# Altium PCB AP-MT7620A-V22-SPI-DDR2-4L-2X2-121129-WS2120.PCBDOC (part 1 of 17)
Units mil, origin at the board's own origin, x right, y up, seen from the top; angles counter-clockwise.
Board outline 7316 x 4279 mil, 4 copper layers (Top, Inner Layer 2, Inner Layer 3, Bottom), stack 35.4 mil thick; 640 components, 473 nets, 2041 pads, 2358 vias.
Unrouted connection lines stored in the file: 11.
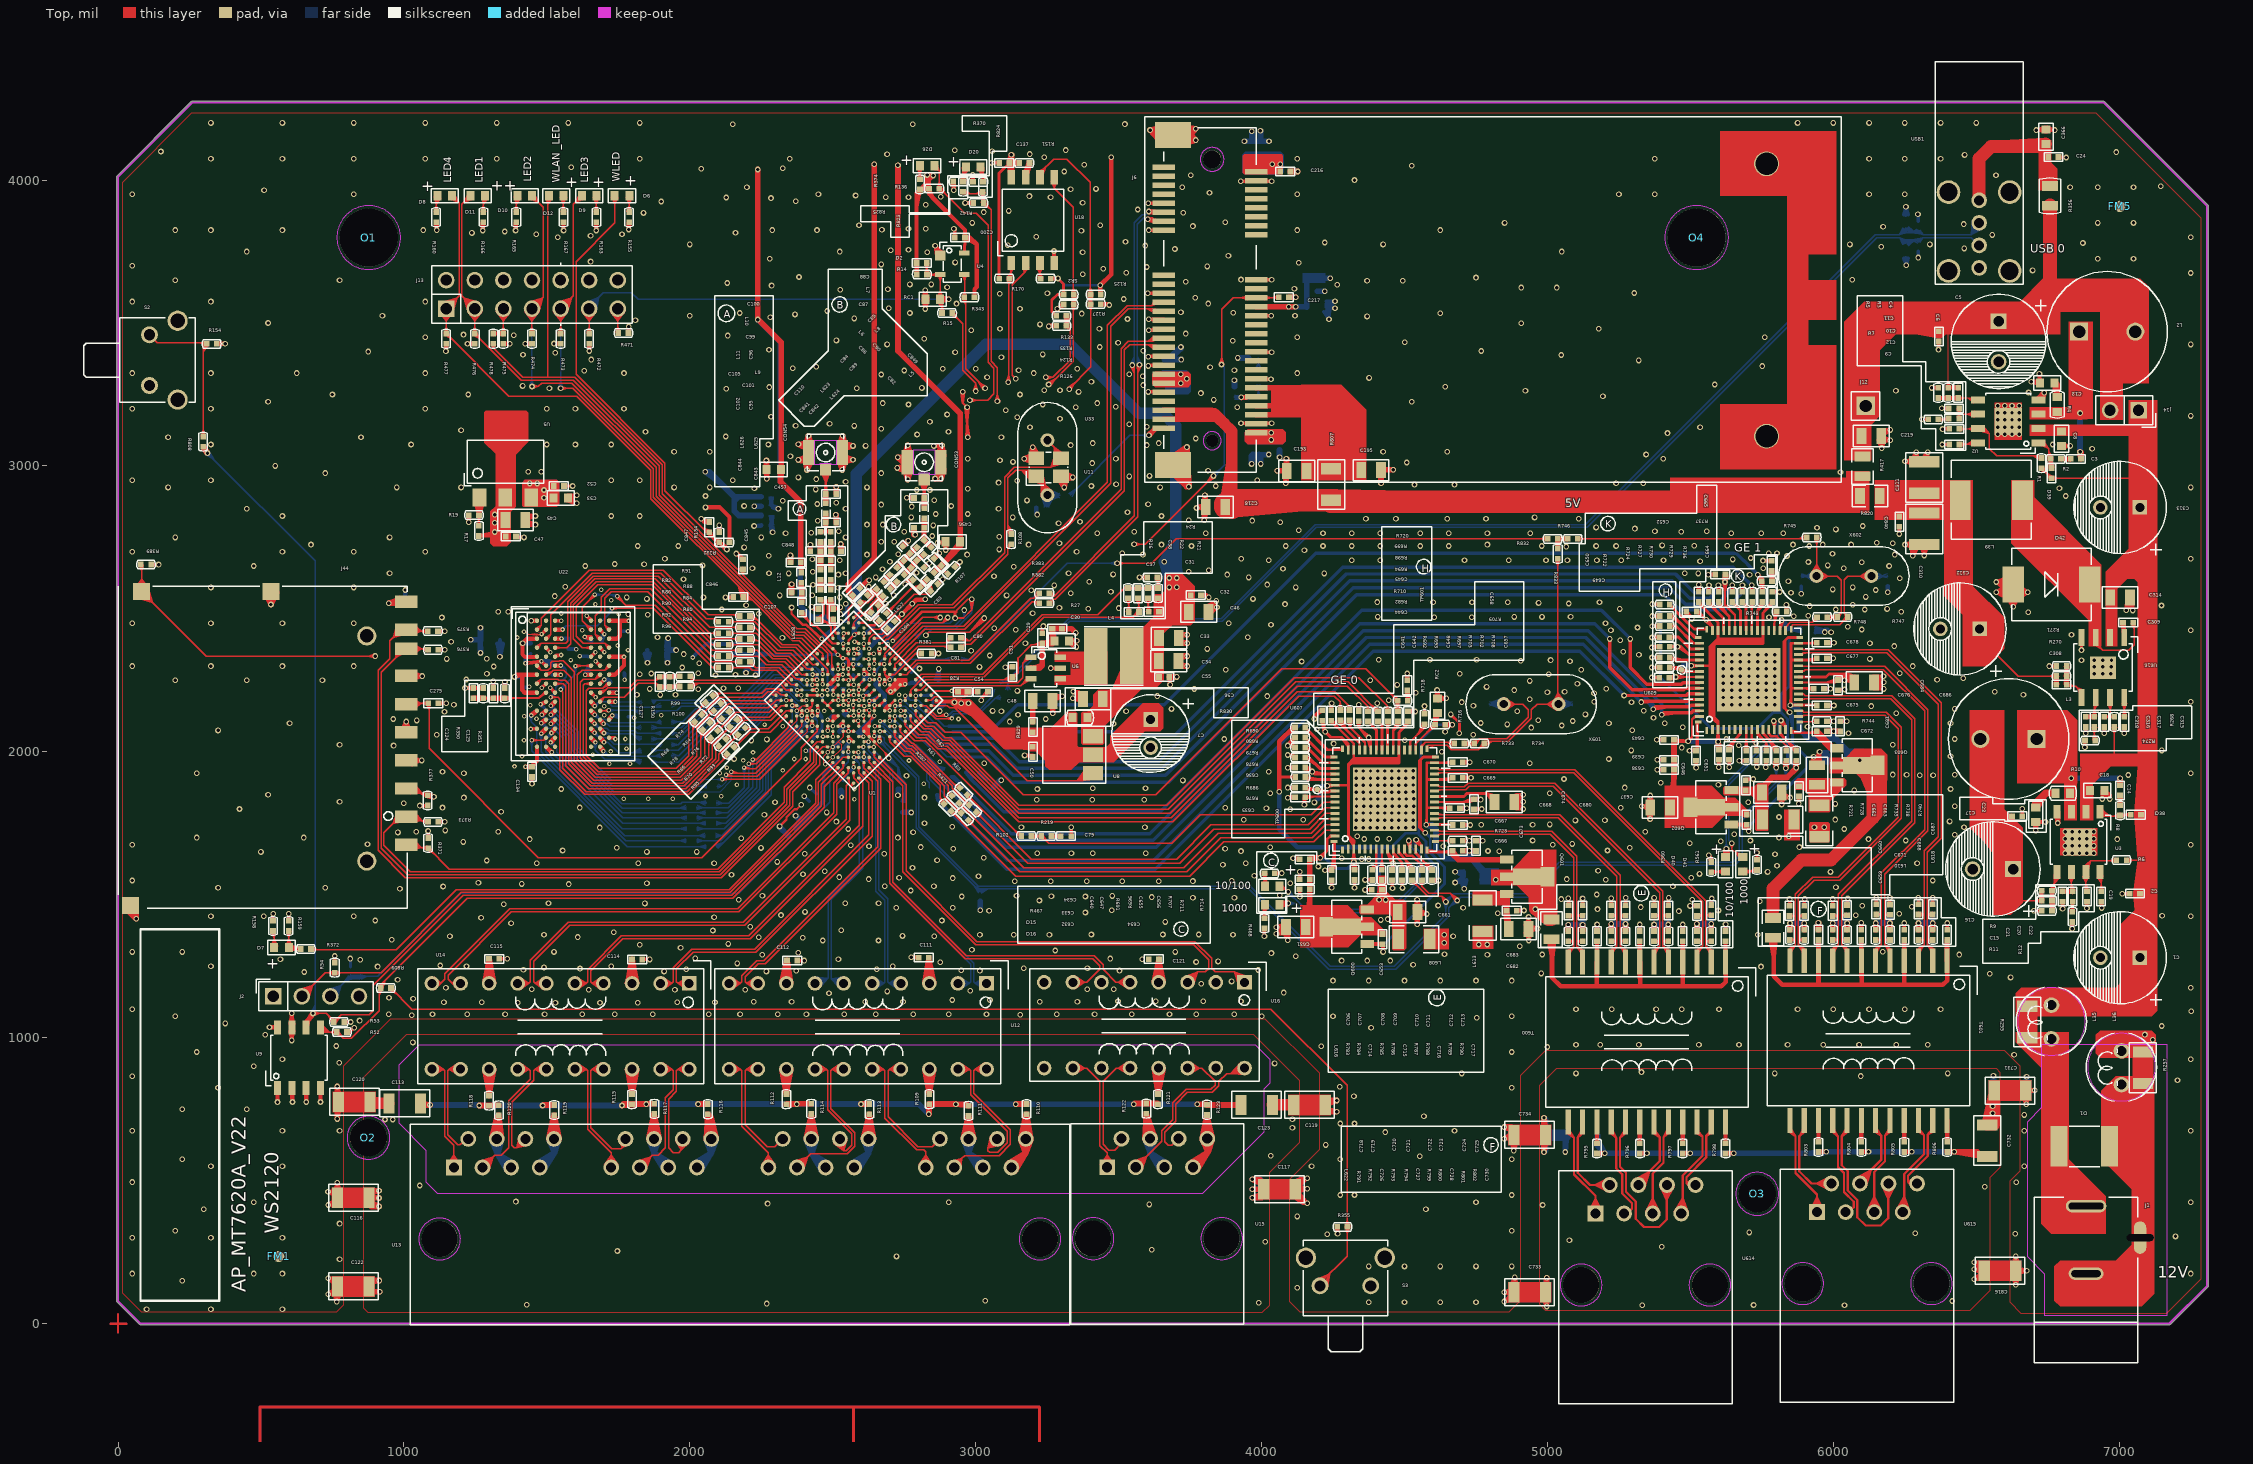
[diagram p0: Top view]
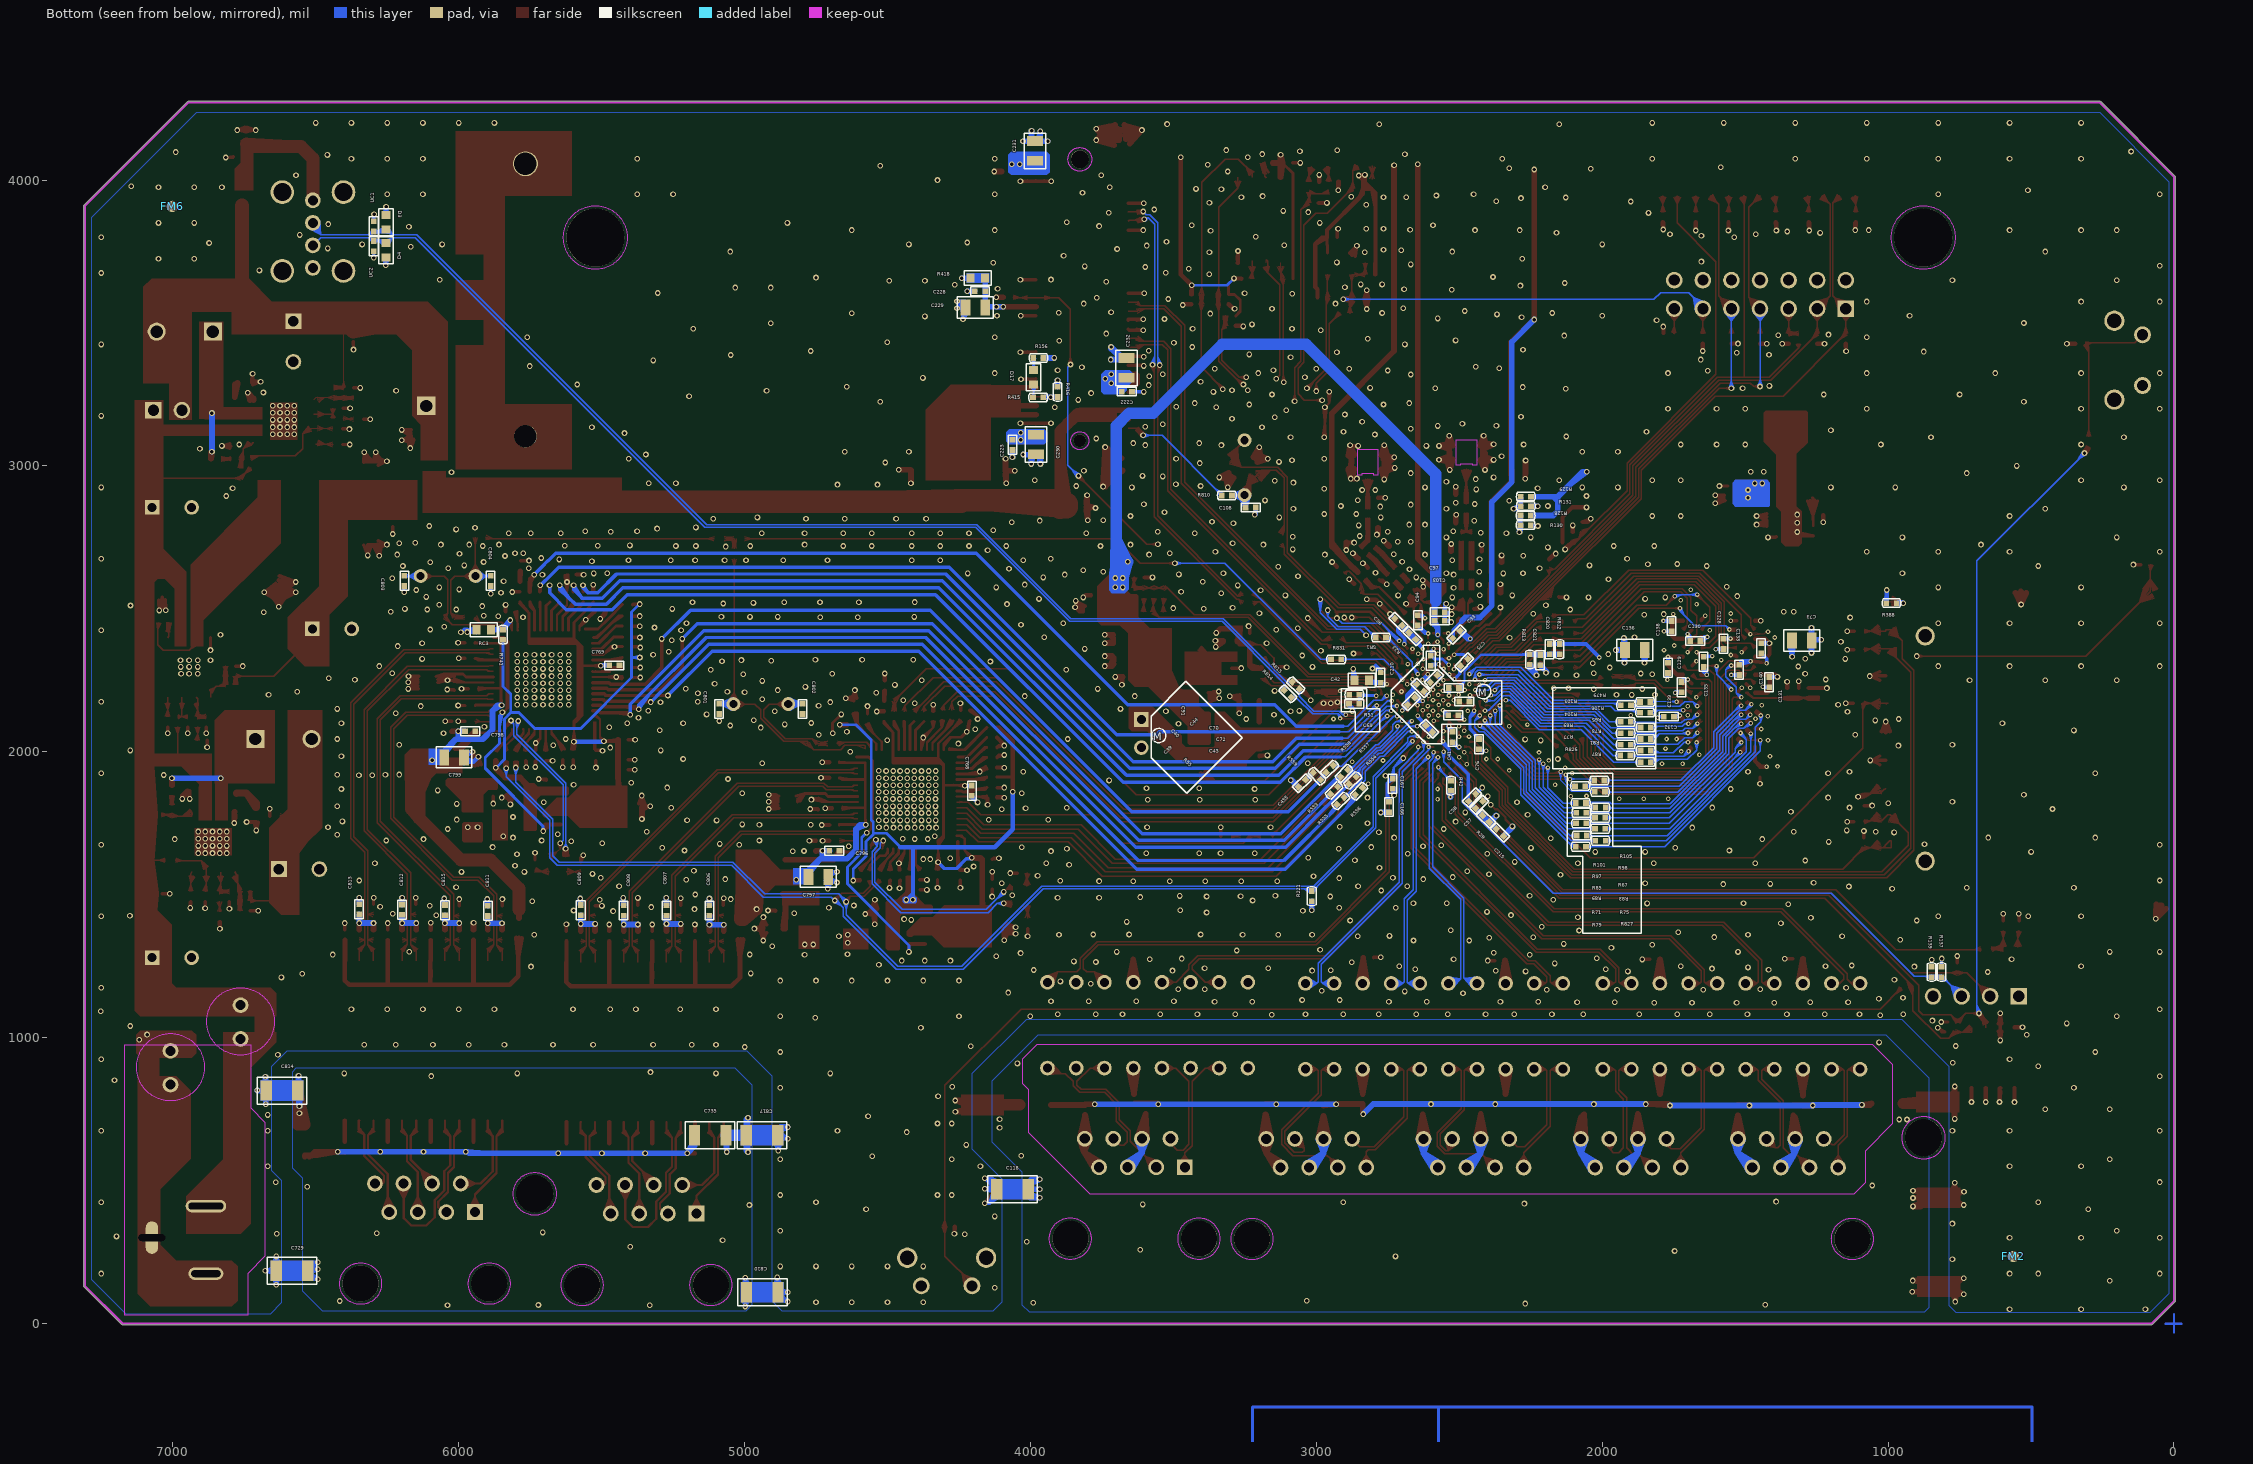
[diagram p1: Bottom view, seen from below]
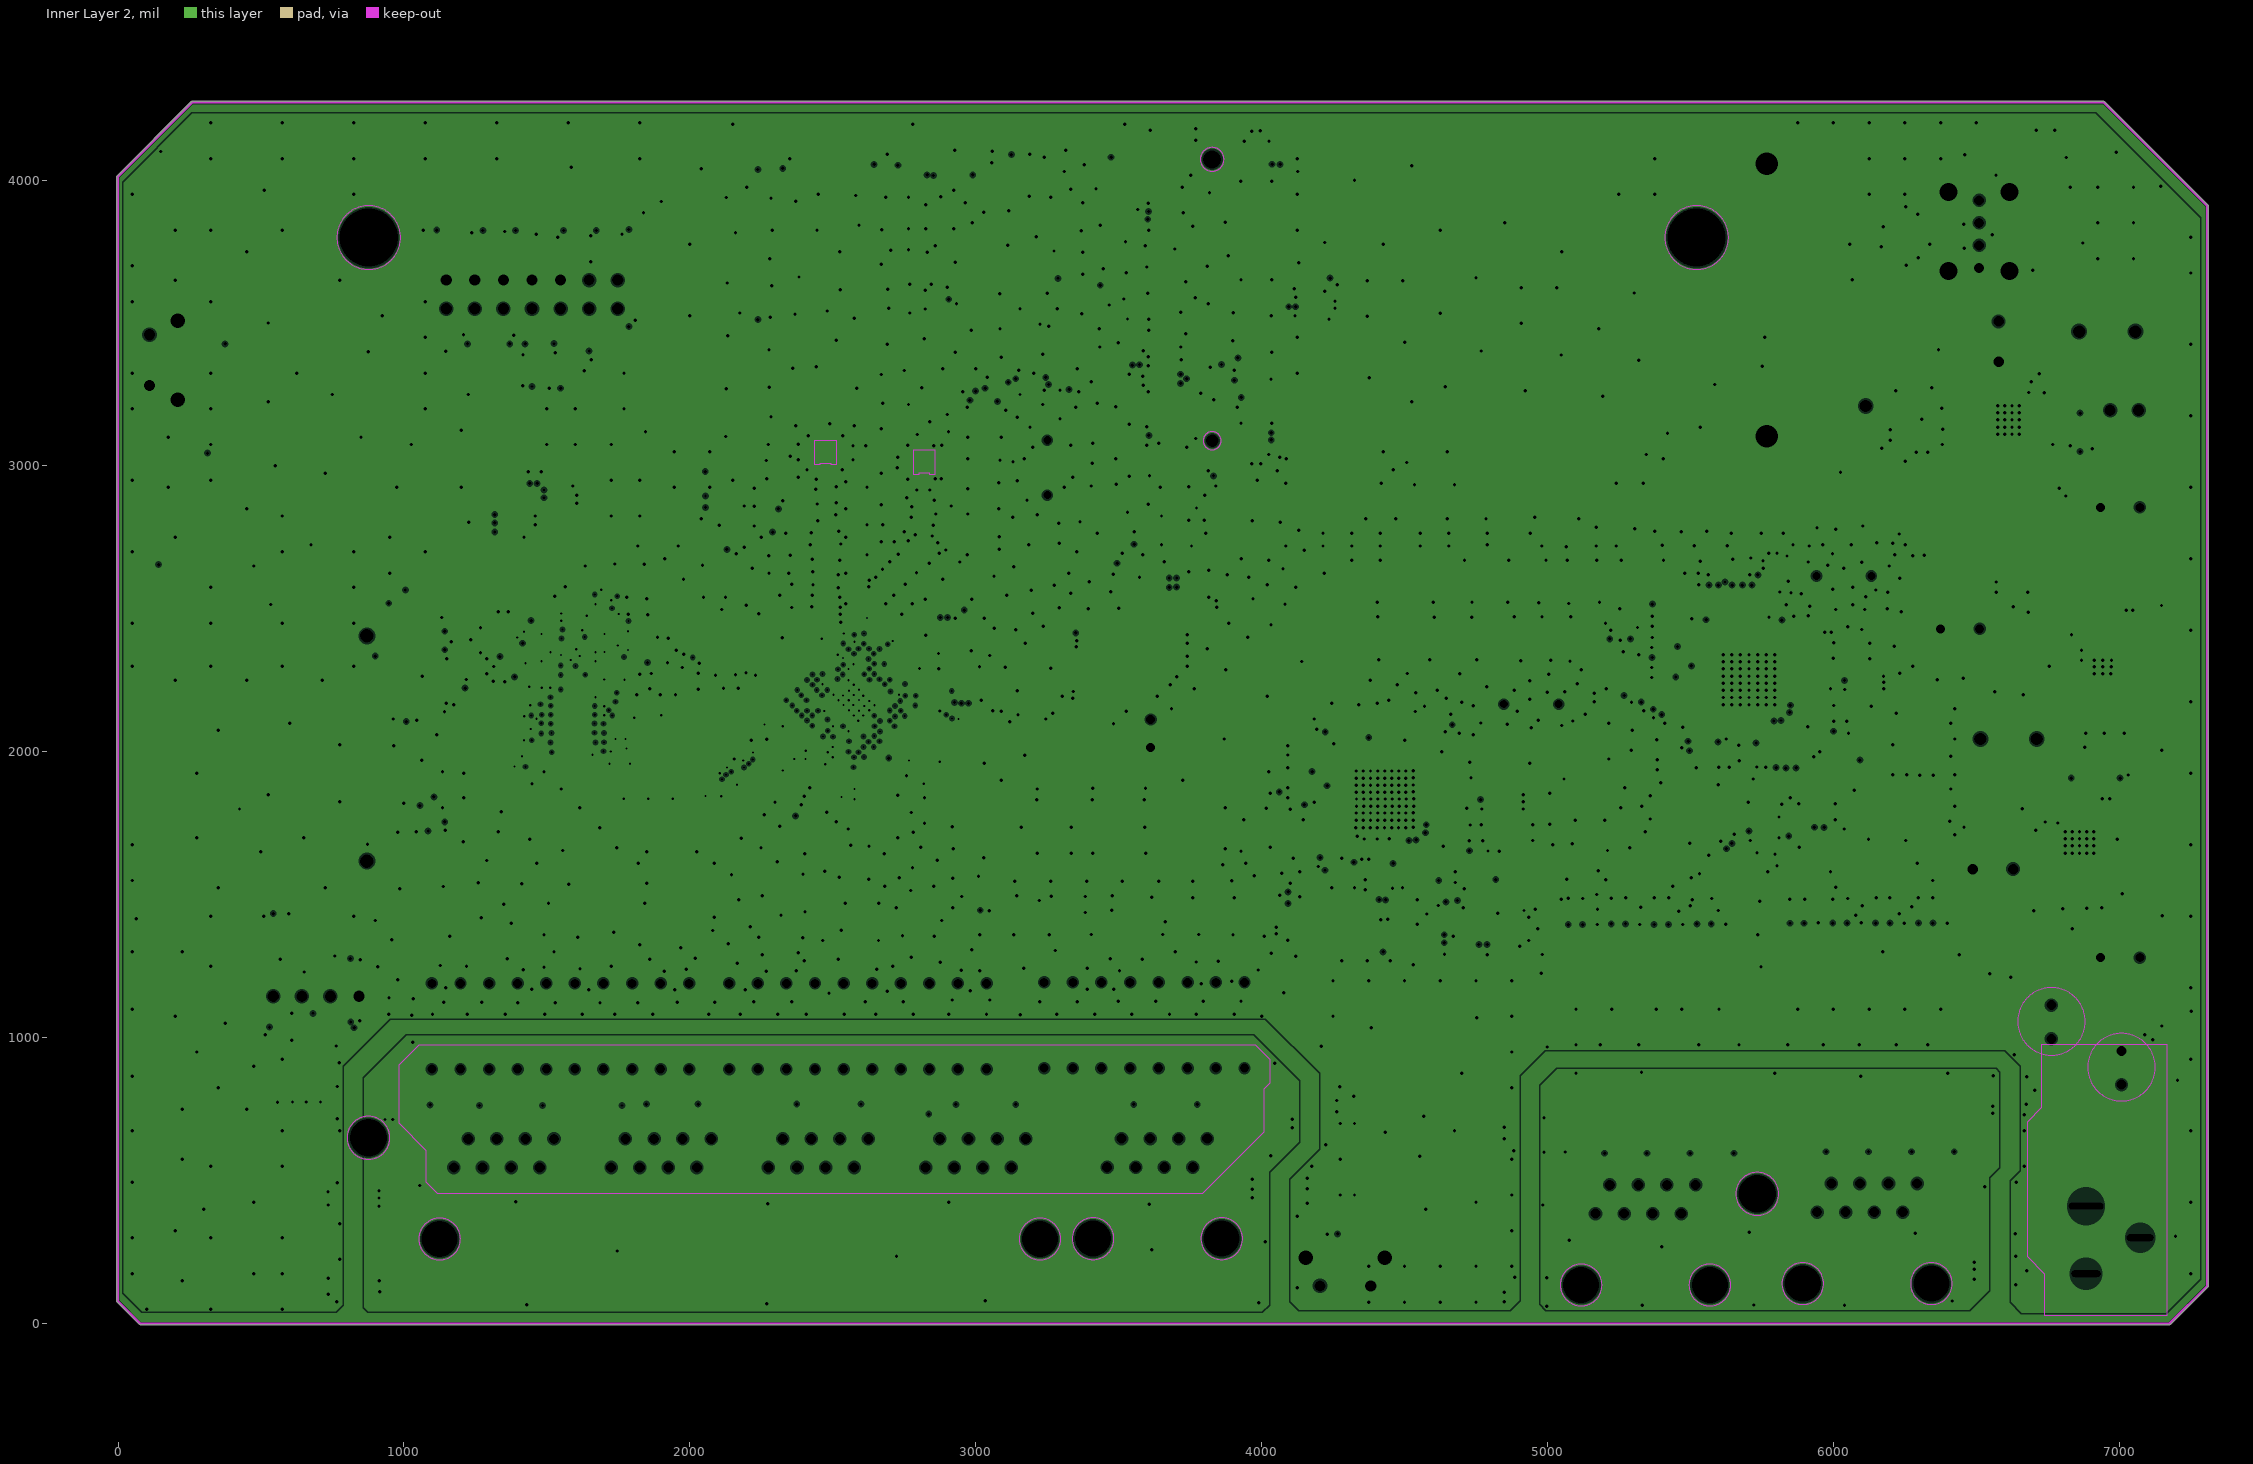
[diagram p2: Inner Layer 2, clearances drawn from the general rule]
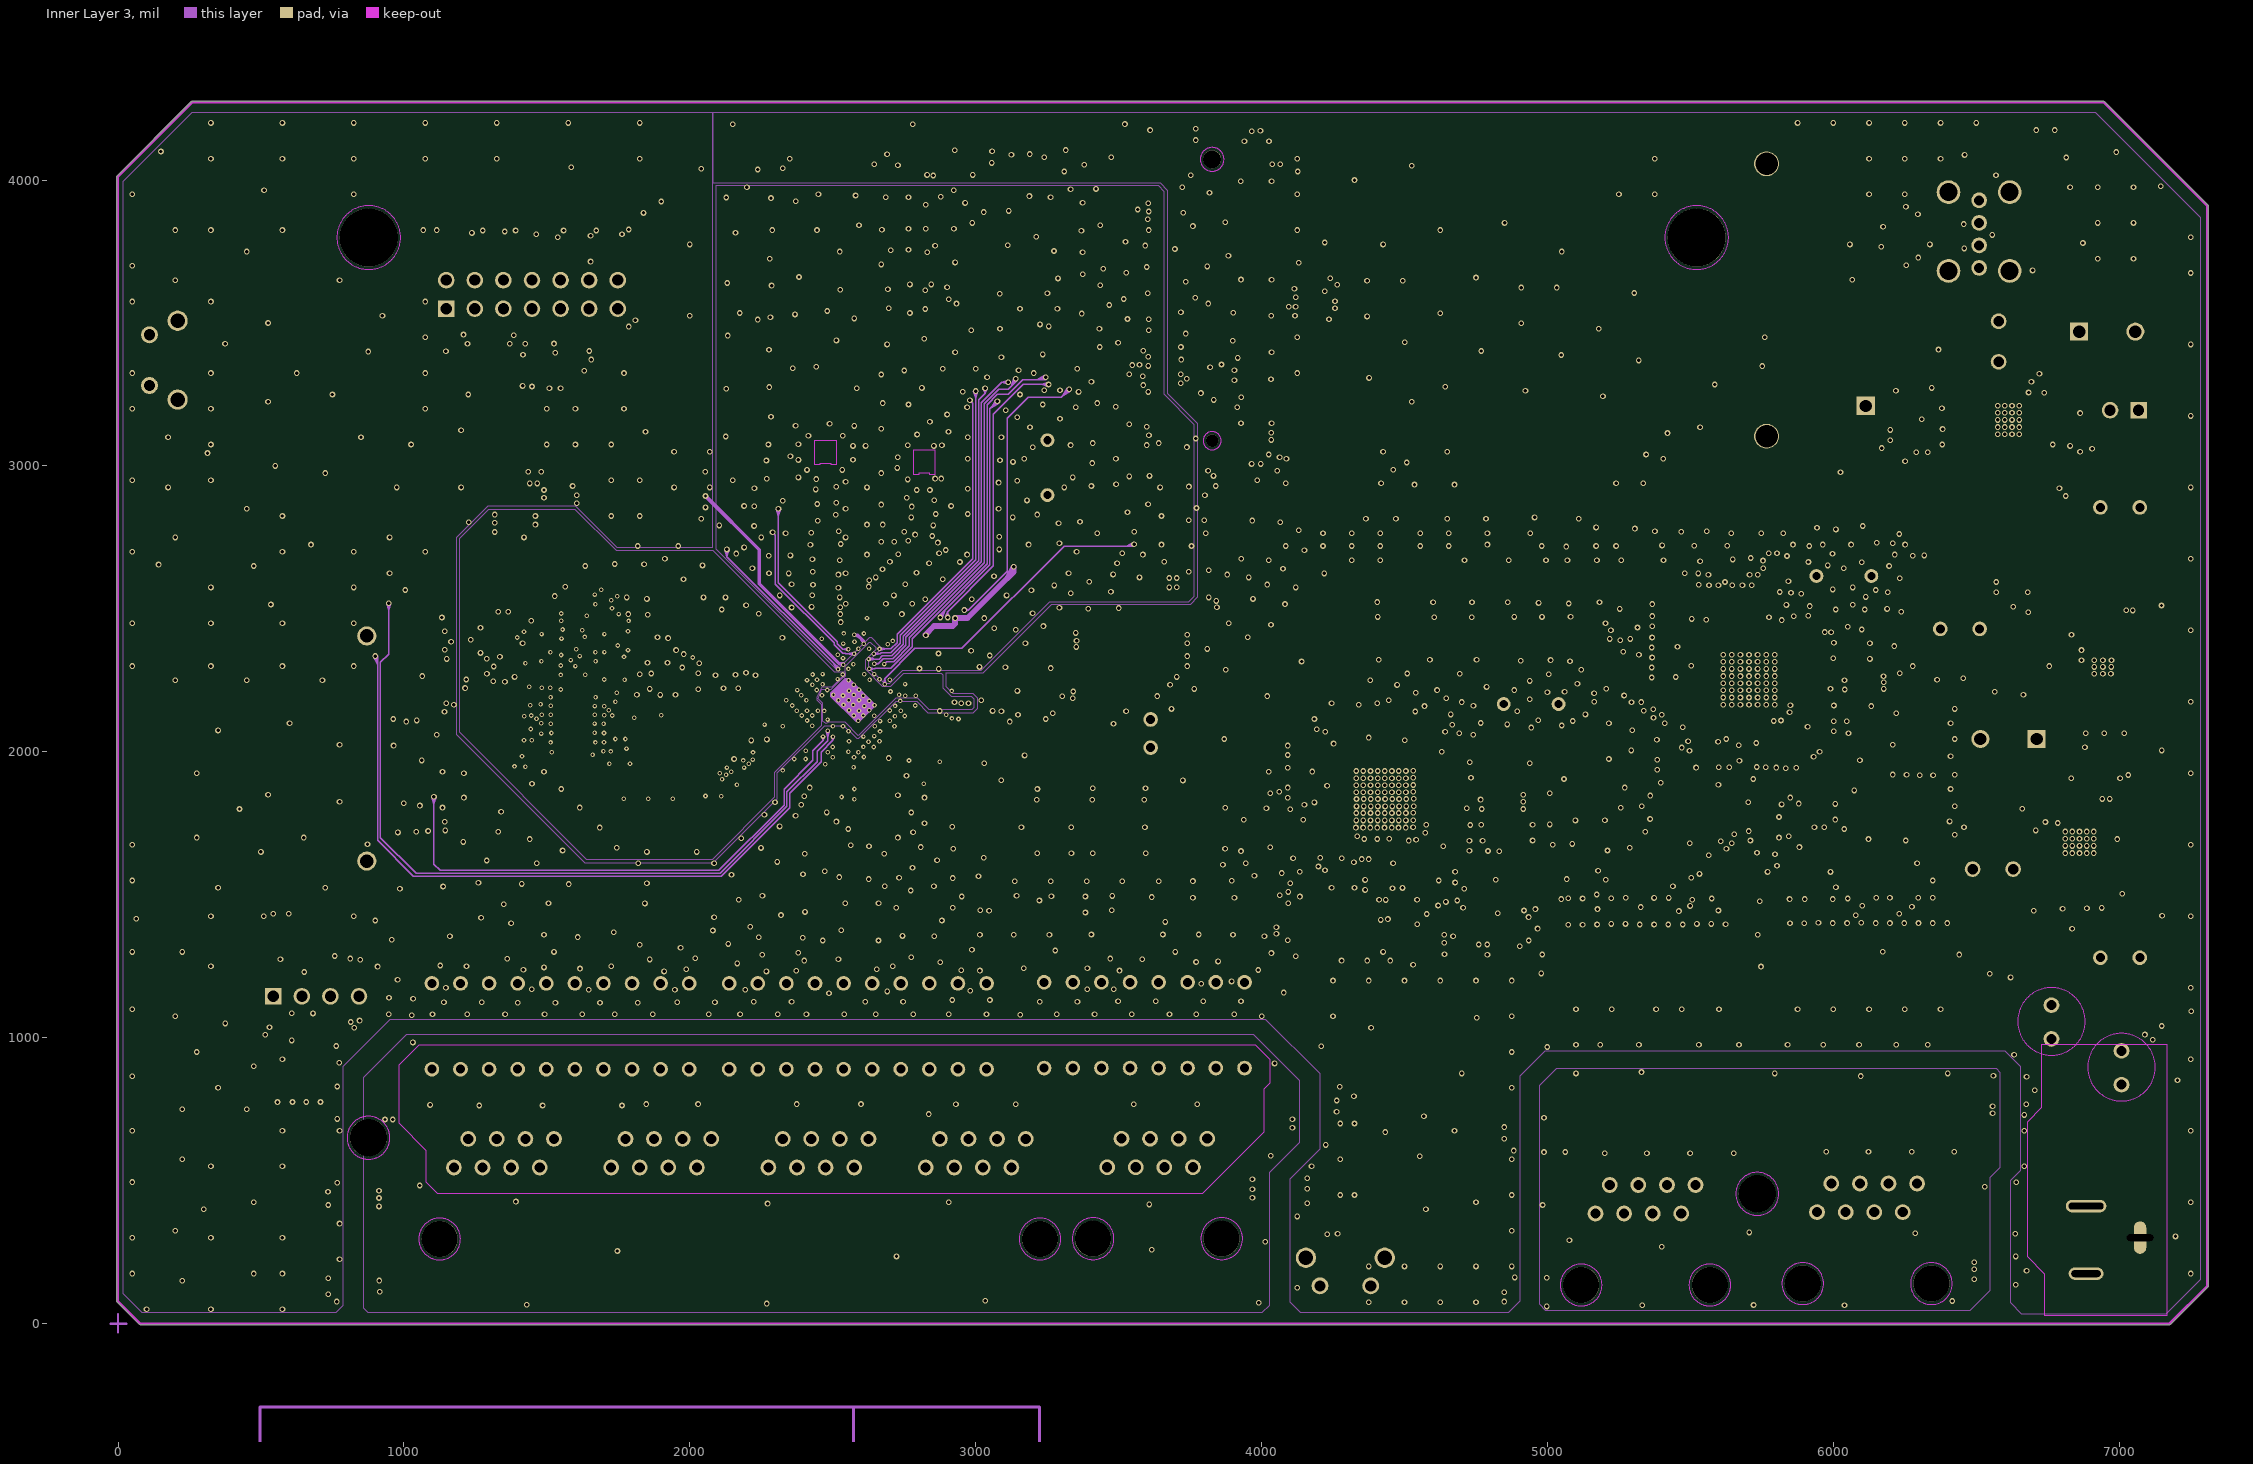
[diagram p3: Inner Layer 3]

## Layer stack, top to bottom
Top: signal copper 1.35
Dielectric: dielectric 10, FR-4, Dk 4.3
Inner Layer 2: plane copper 1.35
Dielectric: dielectric 10, FR-4, Dk 4.3
Inner Layer 3: signal copper 1.35
Dielectric: dielectric 10, FR-4, Dk 4.3
Bottom: signal copper 1.35

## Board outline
-4,78 -2.83,75.17 -2.82,75.16 75.16,-2.82 75.17,-2.83 78,-4 7176,-4 7178.83,-2.83 7178.84,-2.82 7310.82,129.16 7310.83,129.17 7312,132 7312,3909.06 7310.83,3911.89 6948.8,4273.83 6945.97,4275 258.77,4275 255.94,4273.83 -2.83,4014.66 -4,4011.84

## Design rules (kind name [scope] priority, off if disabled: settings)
Clearance "'Classon Layer' PADS rule_125" [InNetClass('DDR') And OnLayer('Top')] p1: gap=7
Clearance "'Classon Layer' PADS rule_124" [InNetClass('DDR') And OnLayer('Top') And IsSMTPin vs IsSMTPin] p2: gap=7
Clearance "'Classon Layer' PADS rule_123" [InNetClass('DDR') And OnLayer('Top')] p3: gap=5
Clearance "'Classon Layer' PADS rule_122" [InNetClass('DDR') And OnLayer('Top') And (IsTrack Or IsArc) vs (IsTrack Or IsArc)] p4: gap=5
Clearance "'Classon Layer' PADS rule_121" [InNetClass('DDR') And OnLayer('Top') vs (IsTrack Or IsArc Or IsThruPin Or IsSMTPin Or IsVia Or IsFill Or InPolygon)] p5: gap=4
Clearance "'Classon Layer' PADS rule_119" [InNetClass('ETH_20') And OnLayer('Bottom')] p6: gap=7
Clearance "'Classon Layer' PADS rule_118" [InNetClass('ETH_20') And OnLayer('Bottom') And IsSMTPin vs IsSMTPin] p7: gap=7
Clearance "'Classon Layer' PADS rule_117" [InNetClass('ETH_20') And OnLayer('Bottom')] p8: gap=5
Clearance "'Classon Layer' PADS rule_116" [InNetClass('ETH_20') And OnLayer('Bottom') And (IsTrack Or IsArc) vs (IsTrack Or IsArc)] p9: gap=5
Clearance "'Classon Layer' PADS rule_115" [InNetClass('ETH_20') And OnLayer('Bottom') vs (IsTrack Or IsArc Or IsThruPin Or IsSMTPin Or IsVia Or IsFill Or InPolygon)] p10: gap=4
Clearance "'Classon Layer' PADS rule_113" [InNetClass('PCIE') And OnLayer('Top')] p11: gap=7
Clearance "'Classon Layer' PADS rule_112" [InNetClass('PCIE') And OnLayer('Top') And IsSMTPin vs IsSMTPin] p12: gap=7
Clearance "'Classon Layer' PADS rule_111" [InNetClass('PCIE') And OnLayer('Top')] p13: gap=6
Clearance "'Classon Layer' PADS rule_110" [InNetClass('PCIE') And OnLayer('Top') And (IsTrack Or IsArc) vs (IsTrack Or IsArc)] p14: gap=6
Clearance "'Classon Layer' PADS rule_109" [InNetClass('PCIE') And OnLayer('Top') vs (IsTrack Or IsArc Or IsThruPin Or IsSMTPin Or IsVia Or IsFill Or InPolygon)] p15: gap=4
Clearance "'Classon Layer' PADS rule_107" [InNetClass('DDR') And OnLayer('Bottom')] p16: gap=7
Clearance "'Classon Layer' PADS rule_106" [InNetClass('DDR') And OnLayer('Bottom') And IsSMTPin vs IsSMTPin] p17: gap=7
Clearance "'Classon Layer' PADS rule_105" [InNetClass('DDR') And OnLayer('Bottom')] p18: gap=5
Clearance "'Classon Layer' PADS rule_104" [InNetClass('DDR') And OnLayer('Bottom') And (IsTrack Or IsArc) vs (IsTrack Or IsArc)] p19: gap=5
Clearance "'Classon Layer' PADS rule_103" [InNetClass('DDR') And OnLayer('Bottom') vs (IsTrack Or IsArc Or IsThruPin Or IsSMTPin Or IsVia Or IsFill Or InPolygon)] p20: gap=4
Clearance "'Classon Layer' PADS rule_101" [InNetClass('ETH_20') And OnLayer('Top')] p21: gap=7
Clearance "'Classon Layer' PADS rule_100" [InNetClass('ETH_20') And OnLayer('Top') And IsSMTPin vs IsSMTPin] p22: gap=7
Clearance "'Classon Layer' PADS rule_99" [InNetClass('ETH_20') And OnLayer('Top')] p23: gap=5
Clearance "'Classon Layer' PADS rule_98" [InNetClass('ETH_20') And OnLayer('Top') And (IsTrack Or IsArc) vs (IsTrack Or IsArc)] p24: gap=5
Clearance "'Classon Layer' PADS rule_97" [InNetClass('ETH_20') And OnLayer('Top') vs (IsTrack Or IsArc Or IsThruPin Or IsSMTPin Or IsVia Or IsFill Or InPolygon)] p25: gap=4
Clearance "'Classon Layer' PADS rule_95" [InNetClass('GE_PHY') And OnLayer('Bottom')] p26: gap=7
Clearance "'Classon Layer' PADS rule_94" [InNetClass('GE_PHY') And OnLayer('Bottom') And IsSMTPin vs IsSMTPin] p27: gap=7
Clearance "'Classon Layer' PADS rule_93" [InNetClass('GE_PHY') And OnLayer('Bottom')] p28: gap=6
Clearance "'Classon Layer' PADS rule_92" [InNetClass('GE_PHY') And OnLayer('Bottom') And (IsTrack Or IsArc) vs (IsTrack Or IsArc)] p29: gap=6
Clearance "'Classon Layer' PADS rule_91" [InNetClass('GE_PHY') And OnLayer('Bottom') vs (IsTrack Or IsArc Or IsThruPin Or IsSMTPin Or IsVia Or IsFill Or InPolygon)] p30: gap=4
Clearance "'Classon Layer' PADS rule_89" [InNetClass('GE_PHY') And OnLayer('Top')] p31: gap=7
Clearance "'Classon Layer' PADS rule_88" [InNetClass('GE_PHY') And OnLayer('Top') And IsSMTPin vs IsSMTPin] p32: gap=7
Clearance "'Classon Layer' PADS rule_87" [InNetClass('GE_PHY') And OnLayer('Top')] p33: gap=6
Clearance "'Classon Layer' PADS rule_86" [InNetClass('GE_PHY') And OnLayer('Top') And (IsTrack Or IsArc) vs (IsTrack Or IsArc)] p34: gap=6
Clearance "'Classon Layer' PADS rule_85" [InNetClass('GE_PHY') And OnLayer('Top') vs (IsTrack Or IsArc Or IsThruPin Or IsSMTPin Or IsVia Or IsFill Or InPolygon)] p35: gap=4
Clearance "'Classon Layer' PADS rule_83" [InNetClass('GE_HP') And OnLayer('Bottom')] p36: gap=7
Clearance "'Classon Layer' PADS rule_82" [InNetClass('GE_HP') And OnLayer('Bottom') And IsSMTPin vs IsSMTPin] p37: gap=7
Clearance "'Classon Layer' PADS rule_81" [InNetClass('GE_HP') And OnLayer('Bottom')] p38: gap=5
Clearance "'Classon Layer' PADS rule_80" [InNetClass('GE_HP') And OnLayer('Bottom') And (IsTrack Or IsArc) vs (IsTrack Or IsArc)] p39: gap=5
Clearance "'Classon Layer' PADS rule_79" [InNetClass('GE_HP') And OnLayer('Bottom') vs (IsTrack Or IsArc Or IsThruPin Or IsSMTPin Or IsVia Or IsFill Or InPolygon)] p40: gap=4
Clearance "'Classon Layer' PADS rule_77" [InNetClass('GE_HP') And OnLayer('Top')] p41: gap=7
Clearance "'Classon Layer' PADS rule_76" [InNetClass('GE_HP') And OnLayer('Top') And IsSMTPin vs IsSMTPin] p42: gap=7
Clearance "'Classon Layer' PADS rule_75" [InNetClass('GE_HP') And OnLayer('Top')] p43: gap=5
Clearance "'Classon Layer' PADS rule_74" [InNetClass('GE_HP') And OnLayer('Top') And (IsTrack Or IsArc) vs (IsTrack Or IsArc)] p44: gap=5
Clearance "'Classon Layer' PADS rule_73" [InNetClass('GE_HP') And OnLayer('Top') vs (IsTrack Or IsArc Or IsThruPin Or IsSMTPin Or IsVia Or IsFill Or InPolygon)] p45: gap=4
Clearance "'Classon Layer' PADS rule_71" [InNetClass('RF') And OnLayer('Bottom')] p46: gap=7
Clearance "'Classon Layer' PADS rule_70" [InNetClass('RF') And OnLayer('Bottom') And IsSMTPin vs IsSMTPin] p47: gap=7
Clearance "'Classon Layer' PADS rule_69" [InNetClass('RF') And OnLayer('Bottom')] p48: gap=5
Clearance "'Classon Layer' PADS rule_68" [InNetClass('RF') And OnLayer('Bottom') And (IsTrack Or IsArc) vs (IsTrack Or IsArc)] p49: gap=5
Clearance "'Classon Layer' PADS rule_67" [InNetClass('RF') And OnLayer('Bottom') vs (IsTrack Or IsArc Or IsThruPin Or IsSMTPin Or IsVia Or IsFill Or InPolygon)] p50: gap=4
Clearance "'Classon Layer' PADS rule_65" [InNetClass('RF') And OnLayer('Top')] p51: gap=7
Clearance "'Classon Layer' PADS rule_64" [InNetClass('RF') And OnLayer('Top') And IsSMTPin vs IsSMTPin] p52: gap=7
Clearance "'Classon Layer' PADS rule_63" [InNetClass('RF') And OnLayer('Top')] p53: gap=5
Clearance "'Classon Layer' PADS rule_62" [InNetClass('RF') And OnLayer('Top') And (IsTrack Or IsArc) vs (IsTrack Or IsArc)] p54: gap=5
Clearance "'Classon Layer' PADS rule_61" [InNetClass('RF') And OnLayer('Top') vs (IsTrack Or IsArc Or IsThruPin Or IsSMTPin Or IsVia Or IsFill Or InPolygon)] p55: gap=4
Clearance "'Classon Layer' PADS rule_59" [InNetClass('PHY_IC') And OnLayer('Bottom')] p56: gap=7
Clearance "'Classon Layer' PADS rule_58" [InNetClass('PHY_IC') And OnLayer('Bottom') And IsSMTPin vs IsSMTPin] p57: gap=7
Clearance "'Classon Layer' PADS rule_57" [InNetClass('PHY_IC') And OnLayer('Bottom')] p58: gap=6
Clearance "'Classon Layer' PADS rule_56" [InNetClass('PHY_IC') And OnLayer('Bottom') And (IsTrack Or IsArc) vs (IsTrack Or IsArc)] p59: gap=6
Clearance "'Classon Layer' PADS rule_55" [InNetClass('PHY_IC') And OnLayer('Bottom') vs (IsTrack Or IsArc Or IsThruPin Or IsSMTPin Or IsVia Or IsFill Or InPolygon)] p60: gap=4
Clearance "'Classon Layer' PADS rule_53" [InNetClass('PHY_IC') And OnLayer('Top')] p61: gap=7
Clearance "'Classon Layer' PADS rule_52" [InNetClass('PHY_IC') And OnLayer('Top') And IsSMTPin vs IsSMTPin] p62: gap=7
Clearance "'Classon Layer' PADS rule_51" [InNetClass('PHY_IC') And OnLayer('Top')] p63: gap=6
Clearance "'Classon Layer' PADS rule_50" [InNetClass('PHY_IC') And OnLayer('Top') And (IsTrack Or IsArc) vs (IsTrack Or IsArc)] p64: gap=6
Clearance "'Classon Layer' PADS rule_49" [InNetClass('PHY_IC') And OnLayer('Top') vs (IsTrack Or IsArc Or IsThruPin Or IsSMTPin Or IsVia Or IsFill Or InPolygon)] p65: gap=4
Clearance "'Classon Layer' PADS rule_47" [InNetClass('USB') And OnLayer('Bottom')] p66: gap=7
Clearance "'Classon Layer' PADS rule_46" [InNetClass('USB') And OnLayer('Bottom') And IsSMTPin vs IsSMTPin] p67: gap=7
Clearance "'Classon Layer' PADS rule_45" [InNetClass('USB') And OnLayer('Bottom')] p68: gap=4.5
Clearance "'Classon Layer' PADS rule_44" [InNetClass('USB') And OnLayer('Bottom') And (IsTrack Or IsArc) vs (IsTrack Or IsArc)] p69: gap=4.5
Clearance "'Classon Layer' PADS rule_43" [InNetClass('USB') And OnLayer('Bottom') vs (IsTrack Or IsArc Or IsThruPin Or IsSMTPin Or IsVia Or IsFill Or InPolygon)] p70: gap=4
Clearance "'Classon Layer' PADS rule_41" [InNetClass('PHY_ETH') And OnLayer('Top')] p71: gap=7
Clearance "'Classon Layer' PADS rule_40" [InNetClass('PHY_ETH') And OnLayer('Top') And IsSMTPin vs IsSMTPin] p72: gap=7
Clearance "'Classon Layer' PADS rule_39" [InNetClass('PHY_ETH') And OnLayer('Top')] p73: gap=6
Clearance "'Classon Layer' PADS rule_38" [InNetClass('PHY_ETH') And OnLayer('Top') And (IsTrack Or IsArc) vs (IsTrack Or IsArc)] p74: gap=6
Clearance "'Classon Layer' PADS rule_37" [InNetClass('PHY_ETH') And OnLayer('Top') vs (IsTrack Or IsArc Or IsThruPin Or IsSMTPin Or IsVia Or IsFill Or InPolygon)] p75: gap=4
Clearance "'Classon Layer' PADS rule_35" [InNetClass('PCIE') And OnLayer('Bottom')] p76: gap=7
Clearance "'Classon Layer' PADS rule_34" [InNetClass('PCIE') And OnLayer('Bottom') And IsSMTPin vs IsSMTPin] p77: gap=7
Clearance "'Classon Layer' PADS rule_33" [InNetClass('PCIE') And OnLayer('Bottom')] p78: gap=5
Clearance "'Classon Layer' PADS rule_32" [InNetClass('PCIE') And OnLayer('Bottom') And (IsTrack Or IsArc) vs (IsTrack Or IsArc)] p79: gap=5
Clearance "'Classon Layer' PADS rule_31" [InNetClass('PCIE') And OnLayer('Bottom') vs (IsTrack Or IsArc Or IsThruPin Or IsSMTPin Or IsVia Or IsFill Or InPolygon)] p80: gap=4
Clearance "'Classon Layer' PADS rule_29" [InNetClass('USB') And OnLayer('Top')] p81: gap=7
Clearance "'Classon Layer' PADS rule_28" [InNetClass('USB') And OnLayer('Top') And IsSMTPin vs IsSMTPin] p82: gap=7
Clearance "'Classon Layer' PADS rule_27" [InNetClass('USB') And OnLayer('Top')] p83: gap=4.5
Clearance "'Classon Layer' PADS rule_26" [InNetClass('USB') And OnLayer('Top') And (IsTrack Or IsArc) vs (IsTrack Or IsArc)] p84: gap=4.5
Clearance "'Classon Layer' PADS rule_25" [InNetClass('USB') And OnLayer('Top') vs (IsTrack Or IsArc Or IsThruPin Or IsSMTPin Or IsVia Or IsFill Or InPolygon)] p85: gap=4
Clearance "'Classon Layer' PADS rule_23" [InNetClass('PHY_ETH') And OnLayer('Bottom')] p86: gap=7
Clearance "'Classon Layer' PADS rule_22" [InNetClass('PHY_ETH') And OnLayer('Bottom') And IsSMTPin vs IsSMTPin] p87: gap=7
Clearance "'Classon Layer' PADS rule_21" [InNetClass('PHY_ETH') And OnLayer('Bottom')] p88: gap=6
Clearance "'Classon Layer' PADS rule_20" [InNetClass('PHY_ETH') And OnLayer('Bottom') And (IsTrack Or IsArc) vs (IsTrack Or IsArc)] p89: gap=6
Clearance "'Classon Layer' PADS rule_19" [InNetClass('PHY_ETH') And OnLayer('Bottom') vs (IsTrack Or IsArc Or IsThruPin Or IsSMTPin Or IsVia Or IsFill Or InPolygon)] p90: gap=4
Clearance "'Default' PADS rule_18" [All] p91: gap=7
Clearance "'Default' PADS rule_17" [IsSMTPin vs IsSMTPin] p92: gap=7
Clearance "'Default' PADS rule_16" [All] p93: gap=4
ComponentClearance "'Default' PADS rule_12" [All] p1: gap=0 collisioncheckmode=3 verticalgap=10 showdistances=FALSE
FlightTimeFalling "'Default' PADS rule_10" [All] p1: maximum=10.00
FlightTimeRising "'Default' PADS rule_9" [All] p1: maximum=10.00
Length "'Default' PADS rule_5" [All] p1: maxlimit=50000 minlimit=0
MatchedLengths "'Default' PADS rule_11" [InNetClass('All Nets')] p1: tolerance=200 checknetsindiffpair=TRUE checkdiffpairvsdiffpair=TRUE checkothers=TRUE
MaxMinImpedance "'Default' PADS rule_8" [All] p1: minimum=50.00 maximum=150.0
ParallelSegment "'Default' PADS rule_7" [All] p1: limit=1000 gap=200
ParallelSegment "'Default' PADS rule_6" [All] p2: limit=1000 gap=200
PlaneClearance "Power Plane Clearance for L35-1" [(Name='L35-1') Or (Name='L35-2') Or (Name='L36-1') Or (Name='L36-2')] p1: clearance=15 // PAD - Power Plane Clearance
PlaneClearance "'Default' PADS rule_14" [All] p2: clearance=6
PlaneConnect "Power Plane Connect Style for L35-1" [(Name='L35-1')] p1: planeconnectstyle=Relief reliefexpansion=10 reliefentries=4 reliefconductorwidth=25 reliefairgap=10
PlaneConnect "Power Plane Connect Style for J6-57" [(Name='J6-57')] p2: planeconnectstyle=Relief reliefexpansion=3.94 reliefentries=4 reliefconductorwidth=15 reliefairgap=0
PlaneConnect "Power Plane Connect Style - pads with no thermal" [(Name='J13-12') Or (Name='J44-H2') Or (Name='J44-H1') Or (Name='J6-55') Or (Name='J6-56') Or (Name='O1-1') Or (Name='O2-1') Or (Name='O3-1') Or (Name='O4-1') Or (Name='U13-33') Or (Name='U13-34') Or (Name='U15-9') Or (Name='U15-10') Or (Name='U16-2') Or (Name='U16-6') Or (Name='U16-8') Or (Name='U16-9') Or (Name='U16-11') Or (Name='U16-15') Or (Name='U614-9') Or (Name='U614-10') Or (Name='U615-9') Or (Name='U615-10')] p3: planeconnectstyle=NoConnect reliefexpansion=20 reliefentries=4 reliefconductorwidth=10 reliefairgap=10 // PAD - No Thermal Connect Rule
PlaneConnect "Power Plane Connect Style - from global settings" [All] p4: planeconnectstyle=Relief reliefexpansion=20 reliefentries=2 reliefconductorwidth=15 reliefairgap=10
PolygonConnect [All] p1: connectstyle=Relief reliefconductorwidth=10 reliefentries=4 polygonreliefangle="90 Angle"
RoutingLayers "'Default' PADS rule_3" [All] p1: top layer_v5=TRUE mid layer 1_v5=TRUE bottom layer_v5=TRUE
RoutingPriority "'Default' PADS rule_2" [All] p1: routingpriority=3
RoutingTopology "'Default' PADS rule" [All] p1: topology=Shortest
RoutingVias "'Default' PADS rule_4" [All] p1: holewidth=12 width=20 viastyle="Through Hole" minholewidth=12 minwidth=20 maxholewidth=12 maxwidth=20
SMDToPlane "'Default' PADS rule_15" [All] p1: distance=20000
SilkscreenOverComponentPads [All] p1: minsilkscreentomaskgap=10
SolderMaskExpansion "Solder Mask Expansion from CAM settings" [All] p1: expansion=2
TestPointUsage [All] p1: valid=0 allowmultiple=FALSE
Testpoint [All] p1: side=15 testpointundercomponent=TRUE minsize=40 maxsize=100 preferedsize=60 minholesize=0 maxholesize=40 preferedholesize=32 testpointgrid=1 style=1023 order=0-112345678
Width "'Classon Layer' PADS rule_120" [InNetClass('DDR') And OnLayer('Top')] p1: maxlimit=200 minlimit=3 preferedwidth=4.5
Width "'Classon Layer' PADS rule_114" [InNetClass('ETH_20') And OnLayer('Bottom')] p2: maxlimit=200 minlimit=3 preferedwidth=20
Width "'Classon Layer' PADS rule_108" [InNetClass('PCIE') And OnLayer('Top')] p3: maxlimit=150 minlimit=3 preferedwidth=5
Width "'Classon Layer' PADS rule_102" [InNetClass('DDR') And OnLayer('Bottom')] p4: maxlimit=200 minlimit=3 preferedwidth=4.5
Width "'Classon Layer' PADS rule_96" [InNetClass('ETH_20') And OnLayer('Top')] p5: maxlimit=200 minlimit=3 preferedwidth=20
Width "'Classon Layer' PADS rule_90" [InNetClass('GE_PHY') And OnLayer('Bottom')] p6: maxlimit=200 minlimit=3 preferedwidth=5
Width "'Classon Layer' PADS rule_84" [InNetClass('GE_PHY') And OnLayer('Top')] p7: maxlimit=200 minlimit=3 preferedwidth=5
Width "'Classon Layer' PADS rule_78" [InNetClass('GE_HP') And OnLayer('Bottom')] p8: maxlimit=200 minlimit=3 preferedwidth=8
Width "'Classon Layer' PADS rule_72" [InNetClass('GE_HP') And OnLayer('Top')] p9: maxlimit=200 minlimit=3 preferedwidth=8
Width "'Classon Layer' PADS rule_66" [InNetClass('RF') And OnLayer('Bottom')] p10: maxlimit=200 minlimit=3 preferedwidth=8
Width "'Classon Layer' PADS rule_60" [InNetClass('RF') And OnLayer('Top')] p11: maxlimit=200 minlimit=3 preferedwidth=8
Width "'Classon Layer' PADS rule_54" [InNetClass('PHY_IC') And OnLayer('Bottom')] p12: maxlimit=200 minlimit=3 preferedwidth=5
Width "'Classon Layer' PADS rule_48" [InNetClass('PHY_IC') And OnLayer('Top')] p13: maxlimit=200 minlimit=3 preferedwidth=5
Width "'Classon Layer' PADS rule_42" [InNetClass('USB') And OnLayer('Bottom')] p14: maxlimit=200 minlimit=3 preferedwidth=5
Width "'Classon Layer' PADS rule_36" [InNetClass('PHY_ETH') And OnLayer('Top')] p15: maxlimit=200 minlimit=3 preferedwidth=5
Width "'Classon Layer' PADS rule_30" [InNetClass('PCIE') And OnLayer('Bottom')] p16: maxlimit=200 minlimit=3 preferedwidth=5
Width "'Classon Layer' PADS rule_24" [InNetClass('USB') And OnLayer('Top')] p17: maxlimit=200 minlimit=3 preferedwidth=5
Width "'Classon Layer' PADS rule" [InNetClass('PHY_ETH') And OnLayer('Bottom')] p18: maxlimit=200 minlimit=3 preferedwidth=5
Width "'Default' PADS rule_13" [All] p19: maxlimit=200 minlimit=3 preferedwidth=4
17 further rules are at their usual default settings.

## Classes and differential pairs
net class DDR: CLK_N CLK_P DDR_BA0 DDR_BA1 DDR_BA2 DDR_CLK_N_1-CPU-RT0 DDR_CLK_P_1-CPU-RT0 DDR_MCKE DDR_MDQM0 DDR_MDQM1 DDR_MDQS0 DDR_MDQS1 DDR_WEN MA1_1-CPU-RT0 MA3_1-CPU-RT0 MA5_1-CPU-RT0 MA7_1-CPU-RT0 MA9_1-CPU-RT0 MA10_1-CPU-RT0 MA12_1-CPU-RT0 MADDR1 MADDR3 MADDR5 MADDR7 MADDR9 MADDR10 MADDR12 MBA0_1-CPU-RT0 MBA1_1-CPU-RT0 MBA2_1-CPU-RT0 MCKE_1-CPU-RT0 MD0_1-CPU-RT0 MD1_1-CPU-RT0 MD2_1-CPU-RT0 MD3_1-CPU-RT0 MD4_1-CPU-RT0 MD5_1-CPU-RT0 MD6_1-CPU-RT0 MD7_1-CPU-RT0 MD8_1-CPU-RT0 MD9_1-CPU-RT0 MD10_1-CPU-RT0 MD11_1-CPU-RT0 MD12_1-CPU-RT0 MD13_1-CPU-RT0 MD14_1-CPU-RT0 MD15_1-CPU-RT0 MDATA0 MDATA1 MDATA2 MDATA3 MDATA4 MDATA5 MDATA6 MDATA7 MDATA8 MDATA9 MDATA10 MDATA11 MDATA12 MDATA13 MDATA14 MDATA15 MDQM0_1-CPU-RT0 MDQM1_1-CPU-RT0 MDQS0_1-CPU-RT0 MDQS1_1-CPU-RT0 MWE_N_1-CPU-RT0
net class ETH_20: CHGND CMT0_4-ETHERNET CMT1_4-ETHERNET CMT2_4-ETHERNET CMT3_4-ETHERNET CMT4_4-ETHERNET LANP0_C1_4-ETHERNET LANP0_C2_4-ETHERNET LANP1_C1_4-ETHERNET LANP1_C2_4-ETHERNET LANP2_C1_4-ETHERNET LANP2_C2_4-ETHERNET LANP3_C1_4-ETHERNET LANP3_C2_4-ETHERNET P1_4-ETHERNET WAN_C1_4-ETHERNET WAN_C2_4-ETHERNET
net class GE_HP: GP1_GE_2_4-ETHERNET GP1_GE_4-ETHERNET GP2_GE_2_4-ETHERNET GP2_GE_4-ETHERNET GP3_GE_2_4-ETHERNET GP3_GE_4-ETHERNET GP4_GE_2_4-ETHERNET GP4_GE_4-ETHERNET GP5_GE_2_4-ETHERNET GP5_GE_4-ETHERNET GP6_GE_2_4-ETHERNET GP6_GE_4-ETHERNET GP7_GE_2_4-ETHERNET GP7_GE_4-ETHERNET GP8_GE_2_4-ETHERNET GP8_GE_4-ETHERNET PMCT1_GE_2_4-ETHERNET PMCT1_GE_4-ETHERNET PMCT2_GE_2_4-ETHERNET PMCT2_GE_4-ETHERNET PMCT3_GE_2_4-ETHERNET PMCT3_GE_4-ETHERNET PMCT4_GE_2_4-ETHERNET PMCT4_GE_4-ETHERNET PMCT_HV_GE_4-ETHERNET
net class GE_PHY: CHANNEL_A+ CHANNEL_A+_2 CHANNEL_A- CHANNEL_A-_2 CHANNEL_B+ CHANNEL_B+_2 CHANNEL_B- CHANNEL_B-_2 CHANNEL_C+ CHANNEL_C+_2 CHANNEL_C- CHANNEL_C-_2 CHANNEL_D+ CHANNEL_D+_2 CHANNEL_D- CHANNEL_D-_2
net class PCIE: APCK_RFCKO_N APCK_RFCKO_P APCK_RFCKON_1-CPU-RT0 APCK_RFCKOP_1-CPU-RT0 PCIE_RXN PCIE_RXP PCIE_TX_N PCIE_TX_P PCIE_TXN_1-CPU-RT0 PCIE_TXP_1-CPU-RT0
net class PHY_ETH: MA0+_4-ETHERNET MA0-_4-ETHERNET MA1+_4-ETHERNET MA1-_4-ETHERNET MA2+_4-ETHERNET MA2-_4-ETHERNET MA3+_4-ETHERNET MA3-_4-ETHERNET MA4+_4-ETHERNET MA4-_4-ETHERNET MB0+_4-ETHERNET MB0-_4-ETHERNET MB1+_4-ETHERNET MB1-_4-ETHERNET MB2+_4-ETHERNET MB2-_4-ETHERNET MB3+_4-ETHERNET MB3-_4-ETHERNET MB4+_4-ETHERNET MB4-_4-ETHERNET
net class PHY_IC: RXIM0 RXIM1 RXIM2 RXIM3 RXIM4 RXIP0 RXIP1 RXIP2 RXIP3 RXIP4 TXOM0 TXOM1 TXOM2 TXOM3 TXOM4 TXOP0 TXOP1 TXOP2 TXOP3 TXOP4
net class RF: O_N_1-CPU-RT0 O_N_1_1-CPU-RT0 O_P_1-CPU-RT0 O_P_1_1-CPU-RT0 PA0_OUT+_1-CPU-RT0 PA0_OUT-_1-CPU-RT0 PA0_OUT_1_1-CPU-RT0 PA1_OUT+_1-CPU-RT0 PA1_OUT-_1-CPU-RT0 PA1_OUT_1_1-CPU-RT0 RF0_PA2_1-CPU-RT0 RF0_PA2_1_1-CPU-RT0 RF0_PA_OUTN_1-CPU-RT0 RF0_PA_OUTP_1-CPU-RT0 RF1_PA2_1-CPU-RT0 RF1_PA2_1_1-CPU-RT0 RF1_PA_OUTN_1-CPU-RT0 RF1_PA_OUTP_1-CPU-RT0 RFOUT_G0 RFOUT_G1
net class USB: UPHY0_PADM_0_1-CPU-RT0 UPHY0_PADP_0_1-CPU-RT0

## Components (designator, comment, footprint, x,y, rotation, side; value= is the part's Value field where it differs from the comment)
C1 "C680UF6.3V/D8H11" C680UF6.3V/D8H11 7003,1280 r180 top
C2 "C0402" C0402 7055,1504 r180 top
C3 "C0402" C0402 6848,3025 r0 top
C4 "C0402" C0402 6437,3256 r270 top
C5 "C470UF16V/D8H11" C470UF16V/D8H11 6578,3435 r270 top
C6 "C0402" C0402 6369,3453 r270 top
C7 "C100UF25V/D6.3H11.5" C100UF25V/D6.3H11.5 3612,2064 r270 top
C8 "C0603" C0603 6798,3095 r270 top
C9 "C0402" C0402 6423,3075 r180 top
C10 "C0402" C0402 6422,3166 r180 top
C11 "C0402" C0402 6422,3201 r180 top
C12 "C0402" C0402 6423,3130 r180 top
C13 "C0603" C0603 6748,3290 r180 top
C14 "C0402" C0402 7003,1865 r90 top
C15 "C0402" C0402 6747,1479 r0 top
C16 "C470UF16V/D8H11" C470UF16V/D8H11 6558,1590 r180 top
C17 "C0402" C0402 6643,1775 r0 top
C18 "C0603" C0603 6923,1865 r0 top
C19 "C0402" C0402 6937,1494 r270 top
C20 "C0402" C0402 6837,1494 r270 top
C21 "C0402" C0402 6802,1494 r270 top
C22 "C0402" C0402 6887,1494 r270 top
C23 "C0603" C0603 6708,1780 r270 top
C24 "C0402" C0402 6770,4081 r0 top
C29 "C0402" C0402 3233,2397 r90 top
C30 "C0603" C0603 3301,2388 r0 top
C31 "C0402" C0402 3623,2490 r180 top
C32 "C0402" C0402 3770,2548 r0 top
C33 "C0805" C0805 3676,2398 r0 top
C34 "C0805" C0805 3675,2318 r0 top
C36 "C0402" C0402 2713,2454 r45 bottom
C37 "C0402" C0402 3553,2489 r180 top
C38 "C0402" C0402 3568,2555 r90 top
C39 "C0402" C0402 2668,2177 r135 bottom
C40 "C0402" C0402 2636.3,2223.8 r224.47 bottom
C41 "C0402" C0402 2524,2052 r270 bottom
C42 "C0603" C0603 2841.5,2250.5 r0 bottom
C43 "C0402" C0402 2521,2128 r0 bottom
C44 "C0402" C0402 2589,2255.5 r135 bottom
C45 "C0805" C0805 1390,2811 r0 top
C46 "C0805" C0805 3780,2490 r0 top
C47 "C0402" C0402 1374,2753 r0 top
C48 "C0805" C0805 3234,2178 r0 top
C50 "C0402" C0402 3200,2000 r270 top
C51 "C0402" C0402 3129,2280 r90 top
C52 "C0402" C0402 1542,2930 r0 top
C53 "C0603" C0603 1549,2888 r0 top
C54 "C0402" C0402 3025,2210 r0 top
C55 "C0402" C0402 3659,2262 r0 top
C56 "C0805" C0805 3410,2185 r180 top
C57 "C0402" C0402 2430,1815 r135 bottom
C58 "C0402" C0402 2455,1840 r135 bottom
C69 "C0402" C0402 2868,2168 r180 bottom
C70 "C0402" C0402 2519,2223 r0 bottom
C72 "C0402" C0402 2482,2176 r0 bottom
C73 "C0805" C0805 1302,2390 r180 bottom
C75 "C0402" C0402 2482.5,2312.5 r135 bottom
C76 "C0402" C0402 2431,2027 r270 bottom
C79 "C0402" C0402 3316,1705 r180 top
C80 "C0402" C0402 2931,2399 r0 top
C81 "C0402" C0402 2931,2366 r0 top
C82 "C0402" C0402 2793,2589 r135 top
C83 "C0402" C0402 2855,2575 r45 top
C84 "C0402" C0402 2712.69,2631.97 r45 top
C85 "C0402" C0402 2807,2727.71 r45 top
C86 "C0402" C0402 2761,2656 r135 top
C87 "C0402" C0402 2802,2784 r180 top
C88 "C0402" C0402 2802,2888 r180 top
C89 "C0402" C0402 2737.44,2607.22 r45 top
C90 "C0402" C0402 2807,2657 r315 top
C91 "C0402" C0402 2599.9,2318.8 r270 bottom
C93 "C0402" C0402 2510,2410 r135 bottom
C94 "C0402" C0402 2645,2460 r90 bottom
C95 "C0402" C0402 2493,2620 r90 top
C96 "C0402" C0402 2493,2752 r90 top
C97 "C0402" C0402 2568.9,2488.7 r180 bottom
C99 "C0402" C0402 2494,2802 r0 top
C100 "C0402" C0402 2494,2902 r0 top
C101 "C0402" C0402 2475,2670 r0 top
C102 "C0402" C0402 2457,2620 r90 top
C103 "C0402" C0402 2568.9,2458.7 r180 bottom
C104 "C0402" C0402 2704,2444 r45 top
C105 "C0402" C0402 2439,2702 r180 top
C107 "C0402" C0402 2374,2556 r180 top
C108 "C0402" C0402 3230,2855 r180 bottom
C110 "C0402" C0402 2582,2560 r45 top
C111 "C0402" C0402 2818,1280 r180 top
C112 "C0402" C0402 2358,1270 r0 top
C113 "C1206" C1206 1003,770 r180 top
C114 "C0402" C0402 1816,1274 r0 top
C115 "C0402" C0402 1316,1276 r0 top
C116 "SB/1206" SB/1206 823,440 r0 top
C117 "SB/1206" SB/1206 4063,470 r180 top
C118 "SB/1206" SB/1206 4063,470 r180 bottom
C119 "SB/1206" SB/1206 4168,765 r180 top
C120 "SB/1206" SB/1206 826.5,775.5 r0 top
C121 "C0402" C0402 3623,1275 r180 top
C122 "SB/1206" SB/1206 823,130 r0 top
C123 "C1206" C1206 3983,765 r0 top
C124 "C0402" C0402 1243,2205 r270 top
C125 "C0402" C0402 1313,2205 r90 top
C127 "C0402" C0402 1895,2245 r270 top
C128 "C0402" C0402 1576,2378 r270 bottom
C129 "C0402" C0402 1723,2226 r90 bottom
C130 "C0402" C0402 1674,2388 r0 bottom
C131 "C0402" C0402 1416,2244 r270 bottom
C132 "C0402" C0402 1767,2123 r0 bottom
C133 "C0402" C0402 1521,2287 r90 bottom
C134 "C0402" C0402 1448,1930 r270 top
C135 "C0402" C0402 1645,2315 r90 bottom
C136 "C0805" C0805 1886,2356 r0 bottom
C137 "C0402" C0402 3100,4060 r180 top
C138 "C0402" C0402 1758,2440 r270 bottom
C139 "C0402" C0402 1770,2294 r270 bottom
C140 "C0402" C0402 1444,2362 r270 bottom
C166 "C0402" C0402 2746,1807 r270 bottom
C167 "C0402" C0402 2733,1889 r270 bottom
C193 "C0805" C0805 4123,2982 r180 top
C195 "C0805" C0805 4383,2985 r0 top
C200 "C0402" C0402 2945,3799 r180 top
C210 "C0402" C0402 2775,2260 r90 bottom
C215 "C0402" C0402 2358,1718 r225 bottom
C216 "C0402" C0402 4083,4030 r0 top
C217 "C0402" C0402 4078,3590 r0 top
C218 "C0805" C0805 3839,2856 r180 top
C219 "C0805" C0805 6133,3105 r0 top
C222 "C0402" C0402 3663,3260 r180 bottom
C223 "C0402" C0402 4063,3074 r270 bottom
C228 "C0402" C0402 4176.4,3611 r0 bottom
C229 "C0805" C0805 4193,3555 r0 bottom
C230 "C0805" C0805 3980,3075 r270 bottom
C231 "C0805" C0805 3984,4102 r90 bottom
C232 "C0805" C0805 3664,3343 r90 bottom
C275 "C0402" C0402 1103,2170 r0 top
C308 "C0402" C0402 6798,2235 r0 top
C309 "C0402" C0402 7031,2452 r0 top
C310 "C1210" C1210 6318,2780 r270 top
C311 "C1210" C1210 6318,2960 r90 top
C312 "C330UF25V/D8H11" C330UF25V/D8H11 6443,2430 r180 top
C313 "C330UF25V/D8H11" C330UF25V/D8H11 7003,2855 r180 top
C314 "C0805" C0805 7003,2540 r0 top
C315 "C0402" C0402 7018,2105 r270 top
C316 "C0402" C0402 6913,2105 r270 top
C317 "C0402" C0402 6948,2105 r270 top
C318 "C0402" C0402 6883,2105 r270 top
C366 "C0603" C0603 6744,4152 r90 top
C455 "C0402" C0402 3050,1890 r135 bottom
C456 "C0603" C0603 2920,2735 r180 top
C457 "C0603" C0603 2294,2988 r180 top
C631 "C0805" C0805 4119.99,1388.05 r180 top
C632 "C0402" C0402 4150.99,1519.05 r180 top
C633 "C0402" C0402 4150.99,1554.05 r180 top
C634 "C0402" C0402 4150.99,1624.05 r180 top
C635 "C0402" C0402 4134.99,1841.05 r180 top
C636 "C0402" C0402 4135,1945 r180 top
C637 "C0805" C0805 5393.99,1806.05 r180 top
C638 "C0402" C0402 5424.99,1937.05 r180 top
C639 "C0402" C0402 5424.99,1972.05 r180 top
C640 "C0402" C0402 4245.99,1569.05 r270 top
C641 "C0402" C0402 4212,2127 r90 top
C642 "C0402" C0402 4244,2127 r90 top
C643 "C0402" C0402 5424.99,2042.05 r180 top
C644 "C0402" C0402 5408.99,2259.05 r180 top
C645 "C0402" C0402 5409.99,2368.05 r180 top
C646 "C0402" C0402 5519.99,1987.05 r270 top
C647 "C0402" C0402 4325,1570 r270 top
C648 "C0402" C0402 4340,2125 r90 top
C649 "C0402" C0402 5504,2491 r180 top
C650 "C0402" C0402 5528.99,2542.05 r90 top
C651 "C0402" C0402 5600,1990 r270 top
C652 "C0402" C0402 5605,2620 r180 top
C653 "C0402" C0402 4422.99,1345.05 r90 top
C654 "C0402" C0402 4403,1518 r180 top
C655 "C0402" C0402 4455.99,1569.05 r270 top
C656 "C0402" C0402 4490.99,1569.05 r270 top
C657 "C0402" C0402 4511.99,2124.05 r90 top
C658 "C0402" C0402 4509.59,2232.35 r270 top
C659 "C0402" C0402 5696.99,1763.05 r90 top
C660 "C0402" C0402 5694,1883 r90 top
C661 "C0805" C0805 4510.99,1439.05 r0 top
C662 "C0402" C0402 5729.99,1987.05 r270 top
C663 "C0402" C0402 5764.99,1987.05 r270 top
C664 "C0402" C0402 5785.99,2542.05 r90 top
C665 "C0402" C0402 5783.59,2650.35 r270 top
C666 "C0402" C0402 4685.99,1654.05 r0 top
C667 "C0402" C0402 4685.99,1744.05 r0 top
C668 "C0402" C0402 4676,1803 r0 top
C669 "C0402" C0402 4685.99,1909.05 r0 top
C670 "C0402" C0402 4685.99,1964.05 r0 top
C671 "C0805" C0805 5784.99,1857.05 r0 top
C672 "C0402" C0402 5959.99,2072.05 r0 top
C673 "C0402" C0402 4749.99,1671.05 r90 top
C674 "C0402" C0402 4742.99,1816.05 r270 top
C675 "C0402" C0402 5959.99,2162.05 r0 top
C676 "C0402" C0402 5949,2221 r0 top
C677 "C0402" C0402 5959.99,2327.05 r0 top
C678 "C0402" C0402 5959.99,2382.05 r0 top
C680 "C0805" C0805 4848.99,1824.05 r0 top
C681 "C0402" C0402 6023.99,2089.05 r90 top
C682 "C0805" C0805 4898.99,1381.05 r0 top
C683 "C0402" C0402 4874.99,1444.05 r0 top
C684 "C0402" C0402 6016,2233 r270 top
C686 "C0805" C0805 6107.99,2242.05 r0 top
C687 "C0805" C0805 5943,1919 r90 top
C688 "C0402" C0402 5880,1862 r270 top
C706 "C0402" C0402 5074,1445 r90 top
C707 "C0402" C0402 5123.05,1445 r90 top
C708 "C0402" C0402 5223.05,1445 r90 top
C709 "C0402" C0402 5273.05,1445 r90 top
C710 "C0402" C0402 5373.05,1445 r90 top
C711 "C0402" C0402 5423.05,1445 r90 top
C712 "C0402" C0402 5523,1444 r90 top
C713 "C0402" C0402 5573,1446 r90 top
C714 "C0402" C0402 5173.05,1355.01 r270 top
C715 "C0402" C0402 5323.05,1355.01 r270 top
C716 "C0402" C0402 5473.05,1355.01 r270 top
C717 "C0402" C0402 5623.05,1355.01 r270 top
C718 "C0402" C0402 5847,1444 r90 top
C719 "C0402" C0402 5898,1444 r90 top
C720 "C0402" C0402 5998,1444 r90 top
C721 "C0402" C0402 6048,1446 r90 top
C722 "C0402" C0402 6150,1449 r90 top
C723 "C0402" C0402 6198,1448 r90 top
C724 "C0402" C0402 6298,1449 r90 top
C725 "C0402" C0402 6348,1449 r90 top
C726 "C0402" C0402 5948.05,1360.01 r270 top
C727 "C0402" C0402 6098.05,1360.01 r270 top
C728 "C0402" C0402 6248.05,1360.01 r270 top
C729 "SB/1206" SB/1206 6583,185 r180 bottom
C730 "C0402" C0402 6398,1360 r270 top
C731 "SB/1206" SB/1206 6618,815 r180 top
C732 "C1206" C1206 6538,640 r90 top
C733 "SB/1206" SB/1206 4938,110 r0 top
C734 "SB/1206" SB/1206 4938,660 r0 top
C735 "C1206" C1206 5120.12,658.56 r180 bottom
C768 "C0402" C0402 4205,1864 r270 bottom
C769 "C0402" C0402 5455.5,2302.5 r180 bottom
C796 "C0402" C0402 4685.99,1654.05 r180 bottom
C797 "C0805" C0805 4741.99,1563.05 r180 bottom
C798 "C0402" C0402 5959.99,2072.05 r180 bottom
C799 "C0805" C0805 6015.99,1981.05 r180 bottom
C801 "C0402" C0402 5089,2150 r270 bottom
C802 "C0402" C0402 4797,2150 r270 bottom
C803 "C0402" C0402 6190,2598 r270 bottom
C804 "C0402" C0402 5888,2598 r270 bottom
C806 "C0402" C0402 5123.05,1445 r90 bottom
C807 "C0402" C0402 5273.05,1445 r90 bottom
C808 "C0402" C0402 5423.05,1445 r90 bottom
C809 "C0402" C0402 5573,1446 r90 bottom
C810 "SB/1206" SB/1206 4938,110 r0 bottom
C811 "C0402" C0402 5898,1444 r90 bottom
C812 "C0402" C0402 6198,1448 r90 bottom
C813 "C0402" C0402 6348,1449 r90 bottom
C814 "SB/1206" SB/1206 6618,815 r180 bottom
C815 "C0402" C0402 6048,1446 r90 bottom
C816 "SB/1206" SB/1206 6583,185 r180 top
C817 "SB/1206" SB/1206 4938.68,658.56 r0 bottom
C820 "C0402" C0402 2184,2359 r270 bottom
C821 "C0402" C0402 2217,2321 r270 bottom
C840 "C0402" C0402 6231,2805 r270 top
C841 "C0402" C0402 2609.14,2535.93 r44.21 top
C842 "C0402" C0402 2646.61,2500.28 r45.51 top
C843 "C0402" C0402 2502,2482 r90 top
C844 "C0402" C0402 2450,2482 r90 top
C845 "C0402" C0402 2186,2656 r90 top
C846 "C0402" C0402 2170,2542 r180 top
C847 "C0402" C0402 2068,2786 r90 top
C848 "C0402" C0402 2370,2663 r180 top
C849 "C0402" C0402 2867,2664 r135 top
CON53 "COAXIAL/SMD/CON/V/I-PEX/W08-5801" COAXIAL/SMD/CON/V/I-PEX/W08-5801 2820,3013 r0 top
CON54 "COAXIAL/SMD/CON/V/I-PEX/W08-5801" COAXIAL/SMD/CON/V/I-PEX/W08-5801 2475,3047 r0 top
D1 "VARISTOR/SMD/TVM5B150L103RY" VARISTOR/SMD/TVM5B150L103RY 6878,620 r180 top
D2 "C0402" C0402 2811,3710 r180 top
D3 "C0603" C0603 6254,3852 r270 bottom
D4 "C0603" C0603 6254,3754 r90 bottom
D6 "C0603" C0603 1763,3945 r180 top
D7 "C0603" C0603 572,1316 r0 top
D8 "C0603" C0603 1143,3945 r0 top
D9 "C0603" C0603 1648,3945 r180 top
D10 "C0603" C0603 1423,3945 r0 top
D11 "C0603" C0603 1258,3945 r180 top
D12 "C0603" C0603 1533,3945 r180 top
D15 "C0603" C0603 4038,1530 r180 top
D16 "C0603" C0603 4038,1465 r180 top
D17 "C0603" C0603 3989,3310 r270 bottom
D20 "C0603" C0603 2991,4046 r180 top
D26 "C0603" C0603 2830,4050 r0 top
D38 "C0402" C0402 7058,1780 r180 top
D39 "C0402" C0402 6763,2975 r90 top
D40 "C0603" C0603 5623,1607 r270 top
D41 "C0603" C0603 5683,1607 r270 top
D42 "D/SMD/P6.61/B540C" D/SMD/P6.61/B540C 6763,2585 r0 top
FM1 "FD" FD 562,235 r0 top
FM2 "FD" FD 562,235 r180 bottom
FM5 "FD" FD 7002,3908 r0 top
FM6 "FD" FD 7002,3908 r180 bottom
J1 "DC-JACK/3P/DIP/R/JD003-PF" DC-JACK/3P/DIP/R/JD003-PF 6884,411 r0 top
J2 "DIP4/P2.54" DIP4/P2.54 543,1145 r0 top
J6 "MINI-PCI-EXPRESS/52P/SMD/R/F/C1720007" MINI-PCI-EXPRESS/52P/SMD/R/F/C1720007 3658,4045 r270 top
J12 "P1//M" P1//M 6113,3210 r0 top
J13 "DIP7X2/P2.54" DIP7X2/P2.54 1148,3550 r0 top
J14 "DIP2/P2.54" DIP2/P2.54 7068,3195 r180 top
J44 "CON10P/SMD/R/F/7SDCN-B0-1X14" CON10P/SMD/R/F/7SDCN-B0-1X14 1008,1675 r270 top
L2 "L/IND/DIP/MCD-0808-150MU-J" L/IND/DIP/MCD-0808-150MU-J 6958,3470 r0 top
L3 "L/IND/DIP/MCD-0808-150MU-J" L/IND/DIP/MCD-0808-150MU-J 6613,2045 r180 top
L4 "L/IND/SMD/LVS5045" L/IND/SMD/LVS5045 3483,2335 r0 top
L5 "L0402" L0402 2842,2615 r45 top
L6 "L0402" L0402 2757.5,2706.5 r135 top
L7 "L0402" L0402 2820,2834 r90 top
L8 "L0402" L0402 2831.75,2702.96 r45 top
L9 "L0402" L0402 2511,2702 r0 top
L10 "L0402" L0402 2476,2852 r90 top
L11 "L0402" L0402 2457,2752 r90 top
L12 "L0402" L0402 2390,2609 r90 top
L35 "L/IND/DIP/D6H14" L/IND/DIP/D6H14 6763,1055 r90 top
L36 "L/IND/DIP/D6H14" L/IND/DIP/D6H14 7008,895 r90 top
L39 "L/IND/SMD/GSTD6030PW-6R8M" L/IND/SMD/GSTD6030PW-6R8M 6553,2880 r180 top
L608 "L1206" L1206 4532.99,1345.05 r180 top
L610 "L1206" L1206 5806.99,1763.05 r180 top
L613 "L1206" L1206 4772.99,1427.05 r90 top
L616 "L0805" L0805 5014.05,1379.01 r270 top
L618 "L1206" L1206 5951.24,1758.28 r90 top
L622 "L0805" L0805 5789.05,1384.01 r270 top
L623 "L0402" L0402 2666,2582.14 r45 top
L624 "L0402" L0402 2688.32,2557.39 r45 top
L625 "L0402" L0402 2493,2550 r90 top
L626 "L0402" L0402 2457,2550 r90 top
L627 "L0402" L0402 2676,2472 r45 top
L628 "L0402" L0402 2392,2505 r90 top
O1 "O200" O200 877,3799 r0 top
O2 "O130" O130 876,650 r0 top
O3 "O130" O130 5734,454 r0 top
O4 "O200" O200 5522,3799 r0 top
Q600 "SOT-89/SMD/2SB1386" SOT-89/SMD/2SB1386 4297.99,1388.05 r90 top
Q601 "SOT-89/SMD/2SB1386" SOT-89/SMD/2SB1386 4928.99,1563.05 r270 top
Q602 "SOT-89/SMD/2SB1386" SOT-89/SMD/2SB1386 5571.99,1806.05 r90 top
Q603 "SOT-89/SMD/2SB1386" SOT-89/SMD/2SB1386 6083.5,1952.78 r270 top
R1 "R0402" R0402 6728,3010 r90 top
R2 "R0402" R0402 6778,3025 r180 top
R3 "R0402" R0402 6402,3256 r270 top
R4 "R0603" R0603 6783,3215 r90 top
R5 "R0402" R0402 6367,3256 r90 top
R6 "R0402" R0402 7008,1621 r180 top
R7 "R0402" R0402 6350,3163 r180 top
R8 "R0402" R0402 7003,1795 r270 top
R9 "R0402" R0402 6747,1514 r0 top
R10 "R0603" R0603 6803,1855 r180 top
R11 "R0402" R0402 6747,1444 r180 top
R12 "R0402" R0402 6836,1423 r270 top
R14 "R0402" R0402 2812,3670 r0 top
R15 "R0402" R0402 2900,3535 r0 top
R17 "R0402" R0402 1262,2773 r90 top
R19 "R0402" R0402 1245,2828 r180 top
R21 "R0402" R0402 3638,2555 r90 top
R22 "R0402" R0402 3603,2555 r90 top
R23 "SB/0402" SB/0402 2664,2405 r45 bottom
R24 "R0402" R0402 3618,2610 r180 top
R26 "R0402" R0402 3533,2555 r90 top
R27 "SB/0402" SB/0402 3285,2431 r180 top
R28 "SB/0402" SB/0402 2955,2210 r0 top
R29 "SB/0402" SB/0402 2407,1766 r45 bottom
R42 "R0402" R0402 2529,1882 r90 bottom
R51 "R0402" R0402 2867,2200 r0 bottom
R52 "R0402" R0402 783,1020 r180 top
R53 "R0402" R0402 773,1055 r180 top
R54 "R0402" R0402 758,1245 r90 top
R55 "SB/0402" SB/0402 2605.3,2080.7 r225 bottom
R61 "R0402" R0402 2929.61,1833.54 r135 top
R62 "R0402" R0402 2957.9,1861.82 r135 top
R63 "R0402" R0402 2989.72,1801.72 r135 top
R64 "R0402" R0402 2096.44,2156.57 r45 top
R65 "R0402" R0402 1848,2085 r180 bottom
R66 "R0402" R0402 2085.83,2061.11 r45 top
R67 "R0402" R0402 2006,1805 r180 bottom
R68 "R0402" R0402 2029.26,2117.68 r45 top
R69 "R0402" R0402 1918,2065 r180 bottom
R70 "R0402" R0402 2114.11,2032.83 r45 top
R71 "R0402" R0402 2072,1707 r180 bottom
R72 "R0402" R0402 2153,2100 r45 top
R73 "R0402" R0402 1848,2045 r180 bottom
R74 "R0402" R0402 2068.15,2184.85 r45 top
R75 "R0402" R0402 2007,1731 r180 bottom
R76 "R0402" R0402 2124.72,2128.28 r45 top
R77 "R0402" R0402 1918,2025 r180 bottom
R78 "R0402" R0402 2057.54,2089.39 r45 top
R79 "R0402" R0402 2075,1668 r180 bottom
R80 "R0402" R0402 2193,2355 r0 top
R81 "R0402" R0402 1848,2005 r180 bottom
R82 "R0402" R0402 2118,2455 r0 top
R83 "R0402" R0402 2007,1769 r180 bottom
R84 "R0402" R0402 2193,2395 r0 top
R85 "R0402" R0402 2073,1787 r180 bottom
R86 "R0402" R0402 2118,2415 r0 top
R87 "R0402" R0402 1848,1964 r180 bottom
R88 "R0402" R0402 2193,2435 r0 top
R89 "R0402" R0402 2074,1750 r180 bottom
R90 "R0402" R0402 2118,2375 r0 top
R91 "R0402" R0402 2193,2475 r0 top
R92 "R0402" R0402 2118,2335 r0 top
R93 "R0402" R0402 2181.29,2071.72 r225 top
R94 "R0402" R0402 2193,2315 r180 top
R95 "R0402" R0402 2142.4,2004.54 r225 top
R96 "R0402" R0402 2118,2295 r180 top
R97 "R0402" R0402 2075,1821 r180 bottom
R98 "R0402" R0402 2008,1860 r180 bottom
R99 "R0402" R0402 1983.39,2264.09 r180 top
R100 "R0402" R0402 1983.39,2228.74 r180 top
R101 "R0402" R0402 2077,1880 r180 bottom
R102 "R0402" R0402 3177,1706 r180 top
R103 "R0402" R0402 1917,2163 r180 bottom
R104 "R0402" R0402 1918,2105 r180 bottom
R105 "R0402" R0402 2010,1900 r180 bottom
R106 "R0402" R0402 1850,2137 r180 bottom
R107 "R0402" R0402 2915,2635 r44.9 top
R108 "R0402" R0402 3124,2744 r90 top
R109 "R0402" R0402 2838,785 r90 top
R110 "R0402" R0402 3178,750 r90 top
R111 "R0402" R0402 2975,744 r90 top
R112 "R0402" R0402 2338,785 r90 top
R113 "R0402" R0402 2628,750 r90 top
R114 "R0402" R0402 2425,751 r90 top
R115 "R0402" R0402 1798,785 r90 top
R116 "R0402" R0402 2063,750 r90 top
R117 "R0402" R0402 1876,751 r90 top
R118 "R0402" R0402 1298,780 r90 top
R119 "R0402" R0402 1526,747 r90 top
R120 "R0402" R0402 1332,746 r90 top
R121 "R0402" R0402 3638,785 r90 top
R122 "R0402" R0402 3597,752 r90 top
R123 "R0402" R0402 3809,748 r90 top
R124 "R0402" R0402 3300,3525 r0 top
R125 "R0402" R0402 3420,3600 r180 top
R126 "R0402" R0402 3300,3490 r0 top
R127 "R0402" R0402 3420,3566 r180 top
R128 "R0402" R0402 2268,2826.5 r0 bottom
R129 "R0402" R0402 2267,2892.5 r0 bottom
R130 "R0402" R0402 2268,2793 r0 bottom
R131 "R0402" R0402 2267,2859.5 r0 bottom
R132 "R0402" R0402 2121,2733 r180 top
R133 "R0402" R0402 3325,3600 r0 top
R134 "R0402" R0402 2103,2751 r270 top
R135 "R0402" R0402 3325,3565 r0 top
R136 "R0402" R0402 2855,3970 r0 top
R137 "R0402" R0402 813,1230 r270 bottom
R139 "R0402" R0402 848,1230 r270 bottom
R142 "R0402" R0402 3010,3920 r0 top
R150 "R0402" R0402 1930.36,2245 r270 top
R151 "R0402" R0402 3170,4060 r180 top
R154 "R0402" R0402 327.44,3427.2 r180 top
R155 "R0402" R0402 1788,3870 r270 top
R156 "R0402" R0402 3972,3378 r180 bottom
R158 "R0402" R0402 542,1391 r90 top
R159 "R0402" R0402 597,1391 r270 top
R160 "R0402" R0402 1113,3870 r270 top
R163 "R0402" R0402 1673,3870 r270 top
R165 "R0402" R0402 1393,3870 r270 top
R166 "R0402" R0402 1278,3870 r270 top
R167 "R0402" R0402 1558,3870 r270 top
R170 "R0402" R0402 3100,3655 r180 top
R207 "R0402" R0402 2901.33,1805.25 r135 top
R219 "R0402" R0402 3247,1706 r180 top
R221 "R0402" R0402 3016,1495 r90 bottom
R255 "SB/1206" SB/1206 6678,1055 r90 top
R257 "SB/1206" SB/1206 7083,895 r90 top
R268 "R0402" R0402 6983,2105 r90 top
R270 "R0402" R0402 6798,2265 r0 top
R271 "R0402" R0402 6798,2300 r180 top
R274 "R0402" R0402 6898,2040 r180 top
R343 "R0402" R0402 2978,3590 r180 top
R350 "R0402" R0402 1278,2205 r270 top
R351 "R0402" R0402 1353,2205 r90 top
R355 "R0402" R0402 4283,338.5 r0 top
R356 "R0805" R0805 6758,3945 r90 top
R370 "R0402" R0402 3009,3994 r180 top
R371 "R0402" R0402 1085,1681 r270 top
R372 "R0402" R0402 657,1310 r180 top
R373 "R0402" R0402 1102,1755 r180 top
R374 "R0402" R0402 2805,3985 r270 top
R375 "R0402" R0402 1101,2422 r180 top
R376 "R0402" R0402 1102,2357 r180 top
R377 "R0402" R0402 1083,1830 r90 top
R381 "R0402" R0402 2828,2344 r0 top
R382 "R0402" R0402 3240,2520 r0 top
R383 "R0402" R0402 3240,2555 r0 top
R388 "R0402" R0402 988,2520 r180 bottom
R389 "R0402" R0402 98,2655 r180 top
R415 "R0402" R0402 3973,3240 r180 bottom
R416 "R0402" R0402 3905,3259 r270 bottom
R417 "L0805" L0805 6102.5,2998.5 r90 top
R418 "SB/0603" SB/0603 4183.8,3657.2 r180 bottom
R421 "R0402" R0402 2961.43,1773.43 r135 top
R467 "R0402" R0402 4028,1575 r0 top
R468 "R0402" R0402 4010,1400 r270 top
R471 "R0402" R0402 1768,3465 r180 top
R472 "R0402" R0402 1648,3445 r90 top
R473 "R0402" R0402 1548,3445 r90 top
R474 "R0402" R0402 1448,3445 r90 top
R475 "R0402" R0402 1348,3445 r90 top
R476 "R0402" R0402 1248,3445 r90 top
R477 "R0402" R0402 1148,3445 r90 top
R478 "R0402" R0402 1313,3445 r270 top
R479 "R0402" R0402 1850,2174 r180 bottom
R553 "R0402" R0402 2938,1865 r135 bottom
R554 "R0402" R0402 2873,1900 r135 bottom
R555 "R0402" R0402 2915,1828 r135 bottom
R556 "R0402" R0402 2851,1862 r135 bottom
R557 "R0402" R0402 2903,1925 r135 bottom
R558 "R0402" R0402 2953,1940 r135 bottom
R559 "R0402" R0402 2998,1915 r225 bottom
R560 "R0402" R0402 5573,1597 r90 top
R561 "R0402" R0402 5733,1605 r90 top
R676 "R0402" R0402 4135,1875 r180 top
R678 "R0402" R0402 4135,1980 r180 top
R679 "R0402" R0402 4135,2015 r180 top
R680 "R0402" R0402 4135,2050 r180 top
R682 "R0402" R0402 5410,2295 r180 top
R686 "R0402" R0402 4135.99,1912.05 r0 top
R690 "R0402" R0402 4135,2085 r0 top
R691 "R0402" R0402 4387,1570 r270 top
R692 "R0402" R0402 4276,2128 r270 top
R693 "R0402" R0402 4308,2128 r270 top
R694 "R0402" R0402 5409,2401 r180 top
R696 "R0402" R0402 4420,1570 r90 top
R697 "R0402" R0402 4371.99,2124.05 r270 top
R698 "R0402" R0402 5410,2440 r180 top
R699 "R0402" R0402 5410,2475 r180 top
R702 "R0402" R0402 4441.99,2124.05 r270 top
R703 "R0402" R0402 4406.99,2124.05 r270 top
R707 "R0402" R0402 4525.99,1569.05 r270 top
R708 "R0402" R0402 4476.99,2124.05 r270 top
R709 "R0402" R0402 4493.19,2178.65 r180 top
R710 "R0402" R0402 5409.99,2330.05 r0 top
R711 "R0402" R0402 4560.99,1569.05 r270 top
R714 "R0402" R0402 4595.99,1569.05 r90 top
R716 "R0402" R0402 4625,2095 r0 top
R718 "R0402" R0402 4570,2115 r90 top
R720 "R0402" R0402 5409.99,2515.05 r0 top
R721 "R0402" R0402 5635,1990 r270 top
R722 "R0402" R0402 5563.99,2542.05 r270 top
R723 "R0402" R0402 4685.99,1689.05 r0 top
R724 "R0402" R0402 5598.99,2542.05 r270 top
R727 "R0402" R0402 5645.99,2542.05 r270 top
R728 "R0402" R0402 5694.99,1987.05 r270 top
R729 "R0402" R0402 5715.99,2542.05 r270 top
R730 "R0402" R0402 5680.99,2542.05 r270 top
R733 "R0402" R0402 4692,2029 r0 top
R734 "R0402" R0402 4762,2029 r0 top
R735 "R0402" R0402 5799.99,1987.05 r270 top
R736 "R0402" R0402 5750.99,2542.05 r270 top
R737 "R0402" R0402 5767.19,2596.65 r180 top
R738 "R0402" R0402 5834.99,1987.05 r270 top
R740 "R0402" R0402 5869.99,1987.05 r90 top
R741 "R0402" R0402 5845,2410 r270 bottom
R743 "R0402" R0402 5819,2491 r0 top
R744 "R0402" R0402 5959.99,2107.05 r0 top
R745 "R0402" R0402 5924,2750 r180 top
R746 "R0402" R0402 5088,2745 r0 top
R747 "R0402" R0402 6032,2472 r0 top
R748 "R0402" R0402 5961.01,2470.95 r180 top
R783 "R0402" R0402 5073.05,1355.01 r270 top
R784 "R0402" R0402 5123.05,1355.01 r270 top
R785 "R0402" R0402 5223.05,1355.01 r270 top
R786 "R0402" R0402 5273.05,1355.01 r270 top
R787 "R0402" R0402 5373.05,1355.01 r270 top
R788 "R0402" R0402 5423.05,1355.01 r270 top
R789 "R0402" R0402 5523.05,1355.01 r270 top
R790 "R0402" R0402 5573.05,1355.01 r270 top
R791 "R0402" R0402 5848.05,1360.01 r270 top
R792 "R0402" R0402 5898.05,1360.01 r270 top
R793 "R0402" R0402 5998.05,1360.01 r270 top
R794 "R0402" R0402 6048.05,1360.01 r270 top
R795 "R0402" R0402 5173.05,613.01 r90 top
R796 "R0402" R0402 5323.05,613.01 r90 top
R797 "R0402" R0402 5473.05,613.01 r90 top
R798 "R0402" R0402 5623.05,613.01 r90 top
R799 "R0402" R0402 6148.05,1360.01 r270 top
R800 "R0402" R0402 6198.05,1360.01 r270 top
R801 "R0402" R0402 6298.05,1360.01 r270 top
R802 "R0402" R0402 6348.05,1360.01 r270 top
R803 "R0402" R0402 5948.05,618.01 r90 top
R804 "R0402" R0402 6098.05,618.01 r90 top
R805 "R0402" R0402 6248.05,618.01 r90 top
R806 "R0402" R0402 6398.05,618.01 r90 top
R807 "C1206" C1206 4243,2935 r90 top
R808 "R0402" R0402 298,3085 r270 top
R809 "R0402" R0402 937,1174 r180 top
R810 "R0402" R0402 3313,2897 r0 bottom
R812 "R0402" R0402 2149,2359 r270 bottom
R813 "R0402" R0402 2253,2323 r270 bottom
R814 "R0402" R0402 3100,2203 r225 bottom
R815 "R0402" R0402 3072,2232 r225 bottom
R820 "L0805" L0805 6128,2895 r0 top
R823 "R0402" R0402 2956,3977 r90 top
R824 "R0402" R0402 3025,3976 r90 top
R825 "R0402" R0402 2940,3995 r180 top
R826 "R0402" R0402 1919,1987 r180 bottom
R827 "R0402" R0402 2006,1689 r180 bottom
R829 "C0402" C0402 3200,2087 r90 top
R830 "R0603" R0603 3365,2120 r0 top
R831 "R0402" R0402 2930.5,2323.5 r0 bottom
R832 "R0402" R0402 5018,2745 r180 top
R833 "R0402" R0402 5036,2693 r270 top
RC1 "C0603" C0603 2850,3583 r180 top
RC2 "C0603" C0603 4615,2161 r90 top
RC3 "C0603" C0603 5912,2427 r0 bottom
S2 "SW/4P/DIP/TS02-CN-PF" SW/4P/DIP/TS02-CN-PF 110,3370 r270 top
S3 "SW/4P/DIP/TS02-CN-PF" SW/4P/DIP/TS02-CN-PF 4293,132 r0 top
SR1 "R0402" R0402 2774,2400 r0 bottom
SR2 "R0402" R0402 3245,3655 r180 top
T600 "TRANSFORMER/24P/SMD/HN2429CG" TRANSFORMER/24P/SMD/HN2429CG 5348.05,985.01 r180 top
T601 "TRANSFORMER/24P/SMD/HN2429CG" TRANSFORMER/24P/SMD/HN2429CG 6123.05,990.01 r180 top
TP600 "PAD/1P/0.5MM" PAD/1P/0.5MM 4194.99,1869.05 r90 top
TP601 "PAD/1P/0.5MM" PAD/1P/0.5MM 5468.99,2287.05 r90 top
U1 "MT7620AE2/TFBGA265/P0.65/B0.3/11X11" MT7620AE2/TFBGA265/P0.65/B0.3/11X11 2573,2180 r315 top
U2 "SOP8/SMD/P1.27/IT7653" SOP8/SMD/P1.27/IT7653 6612,3156 r90 top
U3 "SOP8/SMD/P1.27/IT7653" SOP8/SMD/P1.27/IT7653 6858,1685 r180 top
U4 "SOT-143/SMD/G693" SOT-143/SMD/G693 2918,3707 r270 top
U5 "SOT223-3/SMD/P2.3/AX1007" SOT223-3/SMD/P2.3/AX1007 1355,3015 r0 top
U6 "SOT-23-6/SMD/P0.95/APM2701AC" SOT-23-6/SMD/P0.95/APM2701AC 3245,2293 r270 top
U8 "SOT89/SMD" SOT89/SMD 3410,1990 r90 top
U9 "SOIC8/SMD/P1.27/AT24C04B-08B" SOIC8/SMD/P1.27/AT24C04B-08B 633,930 r0 top
U11 "CRYS/SMD/D3.2X2.5/E3SB40/HOSONIC" CRYS/SMD/D3.2X2.5/E3SB40/HOSONIC 3255,2995 r0 top
U12 "TRANSFORMER/20P/DIP/HN2066CG" TRANSFORMER/20P/DIP/HN2066CG 2588,1040 r180 top
U13 "RJ45/32P/DIP/R/N3642-001" RJ45/32P/DIP/R/N3642-001 1175,546 r0 top
U14 "TRANSFORMER/20P/DIP/HN2066CG" TRANSFORMER/20P/DIP/HN2066CG 1548,1040 r180 top
U15 "RJ45/8P/DIP/R/N3612-002" RJ45/8P/DIP/R/N3612-002 3460,547 r0 top
U16 "TRANSFORMER/16P/DIP/HN1674CG" TRANSFORMER/16P/DIP/HN1674CG 3590,1044 r180 top
U18 "SOIC8/SMD/P1.27/AT26DF321" SOIC8/SMD/P1.27/AT26DF321 3200,3860 r0 top
U22 "WBGA84/SMD/P0.8/W9751G6IB" WBGA84/SMD/P0.8/W9751G6IB 1591.55,2238.32 r270 top
U33 "CRYS/DIP/D5X10.6/GB2000025/ECERA" CRYS/DIP/D5X10.6/GB2000025/ECERA 3251,2994 r90 top
U607 "QFN64/SMD/P0.5/IP1001" QFN64/SMD/P0.5/IP1001 4430.99,1834.05 r0 top
U609 "QFN64/SMD/P0.5/IP1001" QFN64/SMD/P0.5/IP1001 5704.99,2252.05 r0 top
U614 "RJ45/8P/DIP/R/8208C-B01" RJ45/8P/DIP/R/8208C-B01 5168.05,385.01 r0 top
U615 "RJ45/8P/DIP/R/8208C-B01" RJ45/8P/DIP/R/8208C-B01 5943.05,390.01 r0 top
U616 "SOP8/SMD/P1.27/RT8251" SOP8/SMD/P1.27/RT8251 6943,2295 r180 top
UC1 "C0402" C0402 6297,3838 r90 bottom
UC2 "C0402" C0402 6297,3769 r270 bottom
USB1 "USB/4P/P2.0/DIP/R/F/SUA-110VB-B2N" USB/4P/P2.0/DIP/R/F/SUA-110VB-B2N 6510,3929 r90 top
X601 "CRYS/DIP/D5X10.6/GB2000025/ECERA" CRYS/DIP/D5X10.6/GB2000025/ECERA 4942.99,2167.05 r180 top
X602 "CRYS/DIP/D5X10.6/GB2000025/ECERA" CRYS/DIP/D5X10.6/GB2000025/ECERA 6036.99,2615.05 r180 top

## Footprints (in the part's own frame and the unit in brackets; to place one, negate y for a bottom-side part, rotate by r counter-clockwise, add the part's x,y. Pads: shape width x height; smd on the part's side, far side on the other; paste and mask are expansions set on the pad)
C100UF25V/D6.3H11.5 [mm]
  rect 1.3x1.3 / inner round 1.3 / far side rect 1.3x1.3 hole 0.8: 1(-1.25,0)
  round 1.3 hole 0.8: 2(1.25,0)
  silkscreen extent -3.45,-3.45 3.45,3.81
C330UF25V/D8H11 [mm]
  rect 1.3x1.3 / inner round 1.3 / far side rect 1.3x1.3 hole 0.8: 1(-1.75,0)
  round 1.3 hole 0.8: 2(1.75,0)
  silkscreen extent -4.1,-4.1 4.1,4.25
C0402 [mil]
  rect 20x20 smd: 1(-18,0) 2(18,0)
  silkscreen extent -33,-15 33,15
C470UF16V/D8H11 [mil]
  rect 55x55 / inner round 55 / far side rect 55x55 hole 37: 1(-70.87,0)
  round 55 hole 37: 2(70.87,0)
  silkscreen extent -165,-165 165,167
C0603 [mil]
  rect 28x32 smd: 1(-25.59,0) 2(25.59,0)
  silkscreen extent -48,-25 48,25
C680UF6.3V/D8H11 [mm]
  rect 1.3x1.3 / inner round 1.3 / far side rect 1.3x1.3 hole 0.8: 1(-1.75,0)
  round 1.3 hole 0.8: 2(1.75,0)
  silkscreen extent -4.1,-4.1 4.1,4.25
C0805 [mil]
  rect 34x56 smd: 1(-34.45,0) 2(34.45,0)
  silkscreen extent -62,-38 62,38
C1206 [mm]
  rect 1x1.8 smd: 1(-1.4,0) 2(1.4,0)
  silkscreen extent -2.2,-1.2 2.2,1.2
C1210 [mm]
  rect 1x2.7 smd: 1(-1.4,0) 2(1.4,0)
  silkscreen extent -2.2,-1.65 2.2,1.65
COAXIAL/SMD/CON/V/I-PEX/W08-5801 [mm]
  rect 1x1.05 smd: 1(0,-1.525)
  rect 1.05x2.2 smd: 2(-1.475,0) 3(1.475,0)
  Keep-Out Layer pour cut-out: -0.95,1.1 0.95,1.1 0.95,-1.1 0.5,-1.1 0.5,-1 -0.5,-1 -0.5,-1.1 -0.95,-1.1 -0.95,1.1
  silkscreen extent -1.63,-1.63 1.63,1.63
